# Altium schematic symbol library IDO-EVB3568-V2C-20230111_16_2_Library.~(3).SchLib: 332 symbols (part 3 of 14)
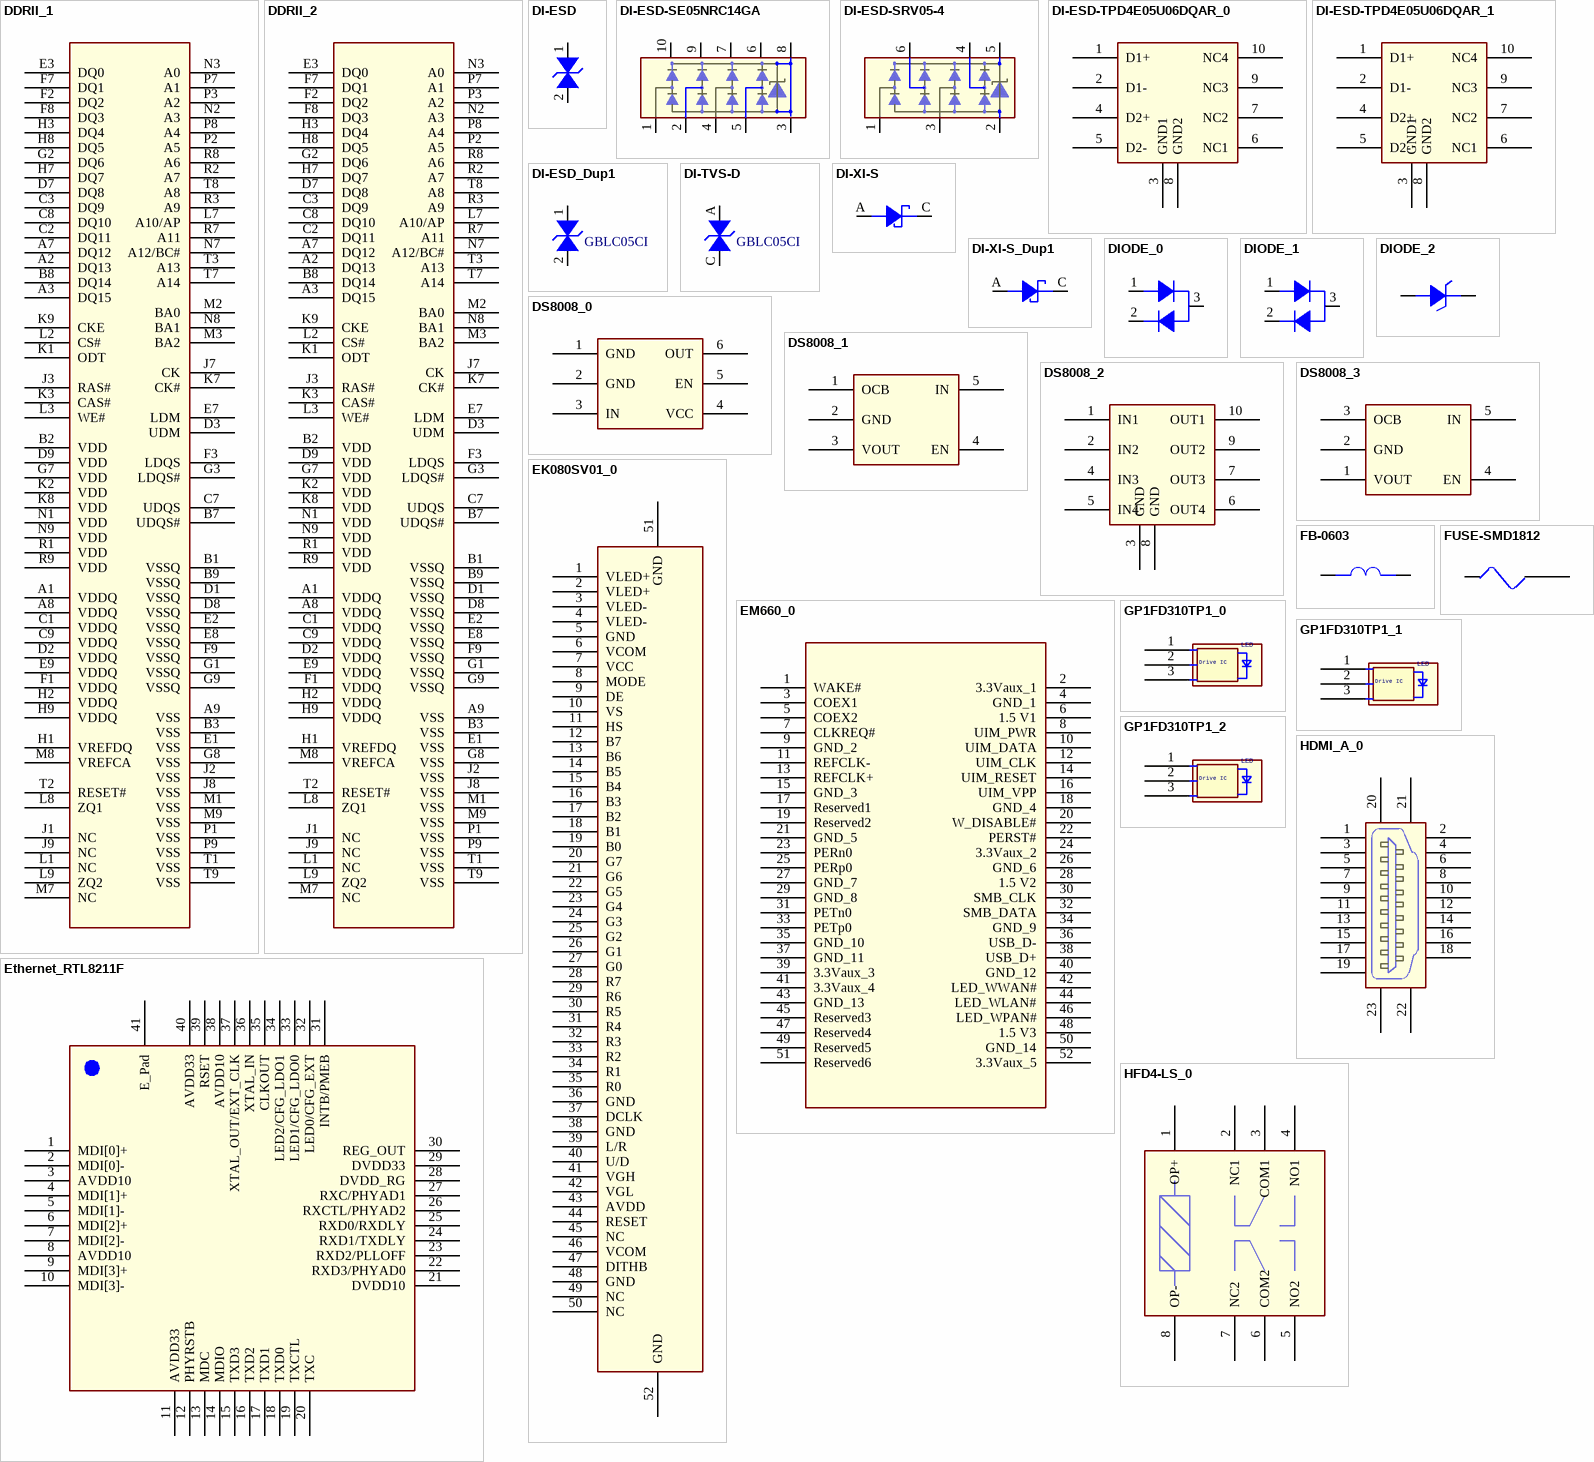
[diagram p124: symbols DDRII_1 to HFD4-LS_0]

## DIODE_1
designator D?
Altium-Right: 30; Altium-Bottom: 40
pins: 1 ANODE, 2 CATHODE, 3 COMMON

## DIODE_2
designator D?
Altium-Right: 30; Altium-Bottom: 20
pins: 1 A, 2 K

## DS8008_0
designator U?
Altium-Right: 70; Altium-Bottom: 60
pins: 1 GND, 2 GND, 3 IN, 4 VCC, 5 EN, 6 OUT

## DS8008_1
designator U?
Altium-Right: 70; Altium-Bottom: 60
pins: 1 OCB, 2 GND, 3 VOUT, 4 EN, 5 IN

## DS8008_2
designator U?
Altium-Right: 70; Altium-Bottom: 80
pins: 1 IN1, 2 IN2, 3 GND (power), 4 IN3, 5 IN4, 6 OUT4, 7 OUT3, 8 GND, 9 OUT2, 10 OUT1

## DS8008_3
designator U?
Altium-Right: 70; Altium-Bottom: 60
pins: 1 VOUT, 2 GND, 3 OCB, 4 EN, 5 IN

## EK080SV01_0
designator J?
Altium-Right: 70; Altium-Bottom: 550
pins: 1 VLED+, 2 VLED+, 3 VLED-, 4 VLED-, 5 GND, 6 VCOM, 7 VCC, 8 MODE, 9 DE, 10 VS, 11 HS, 12 B7, 13 B6, 14 B5, 15 B4, 16 B3, 17 B2, 18 B1, 19 B0, 20 G7, 21 G6, 22 G5, 23 G4, 24 G3, 25 G2, 26 G1, 27 G0, 28 R7, 29 R6, 30 R5, 31 R4, 32 R3, 33 R2, 34 R1, 35 R0, 36 GND, 37 DCLK, 38 GND, 39 L/R, 40 U/D, 41 VGH, 42 VGL, 43 AVDD, 44 RESET, 45 NC, 46 VCOM, 47 DITHB, 48 GND, 49 NC, 50 NC, 51 GND, 52 GND

## EM660_0
designator U?
Altium-Right: 160; Altium-Bottom: 310
pins: 1 WAKE#, 2 3.3Vaux_1 (power), 3 COEX1, 4 GND_1 (power), 5 COEX2, 6 1.5 V1, 7 CLKREQ#, 8 UIM_PWR, 9 GND_2 (power), 10 UIM_DATA, 11 REFCLK-, 12 UIM_CLK, 13 REFCLK+, 14 UIM_RESET, 15 GND_3 (power), 16 UIM_VPP, 17 Reserved1, 18 GND_4 (power), 19 Reserved2, 20 W_DISABLE#, 21 GND_5 (power), 22 PERST#, 23 PERn0, 24 3.3Vaux_2 (power), 25 PERp0, 26 GND_6 (power), 27 GND_7 (power), 28 1.5 V2, 29 GND_8 (power), 30 SMB_CLK, 31 PETn0, 32 SMB_DATA, 33 PETp0, 34 GND_9 (power), 35 GND_10 (power), 36 USB_D-, 37 GND_11 (power), 38 USB_D+, 39 3.3Vaux_3 (power), 40 GND_12, 41 3.3Vaux_4 (power), 42 LED_WWAN#, 43 GND_13 (power), 44 LED_WLAN#, 45 Reserved3, 46 LED_WPAN#, 47 Reserved4, 48 1.5 V3, 49 Reserved5, 50 GND_14 (power), 51 Reserved6, 52 3.3Vaux_5 (power)

## Ethernet_RTL8211F
designator U?
Altium-Right: 230
footprint QFN40_5R00X5R00X0R80_T
pins: 1 MDI[0]+, 2 MDI[0]-, 3 AVDD10 (power), 4 MDI[1]+, 5 MDI[1]-, 6 MDI[2]+, 7 MDI[2]-, 8 AVDD10 (power), 9 MDI[3]+, 10 MDI[3]-, 11 AVDD33 (power), 12 PHYRSTB, 13 MDC, 14 MDIO, 15 TXD3, 16 TXD2, 17 TXD1, 18 TXD0, 19 TXCTL, 20 TXC, 21 DVDD10 (power), 22 RXD3/PHYAD0, 23 RXD2/PLLOFF, 24 RXD1/TXDLY, 25 RXD0/RXDLY, 26 RXCTL/PHYAD2, 27 RXC/PHYAD1, 28 DVDD_RG, 29 DVDD33 (power), 30 REG_OUT, 31 INTB/PMEB, 32 LED0/CFG_EXT, 33 LED1/CFG_LDO0, 34 LED2/CFG_LDO1, 35 CLKOUT, 36 XTAL_IN, 37 XTAL_OUT/EXT_CLK, 38 AVDD10 (power), 39 RSET, 40 AVDD33 (power), 41 E_Pad

## FB-0603
designator FB?
SMD Multilayer Ferrite Chip Bead,3A,30Ohm,0.03R; Part Number: EL4.300Y060300A; Manufacture P/N: PZ1608D300-3R0TF; Manufacture2 P/N: PBY160808T-400Y-N; Manufacturer: SUNLORD; PN Type: SMD FERRITE BEAD; Altium-Right: 40; Altium-Bottom: 20
pins: 1, 2

## FUSE-SMD1812
designator F?
Altium-Right: 30; Altium-Bottom: 20
pins: 1, 2

## GP1FD310TP1_0
designator U?
Altium-Right: 50; Altium-Bottom: 40
pins: 1 GND, 2 Vcc, 3 VIN

## GP1FD310TP1_1
designator U?
Altium-Right: 50; Altium-Bottom: 40
pins: 1 GND, 2 Vcc, 3 VIN

## GP1FD310TP1_2
designator U?
Altium-Right: 50; Altium-Bottom: 40
pins: 1 GND, 2 Vcc, 3 VIN

## HDMI_A_0
designator J?
Altium-Right: 40; Altium-Bottom: 110
pins: 1 $PIN0, 2, 3, 4, 5, 6, 7, 8, 9, 10, 11, 12, 13, 14, 15, 16, 17, 18, 19, 20, 21, 22, 23

## HFD4-LS_0
designator M?
Altium-Right: 120; Altium-Bottom: 110
pins: 1 OP+, 2 NC1, 3 COM1, 4 NO1, 5 NO2, 6 COM2, 7 NC2, 8 OP-

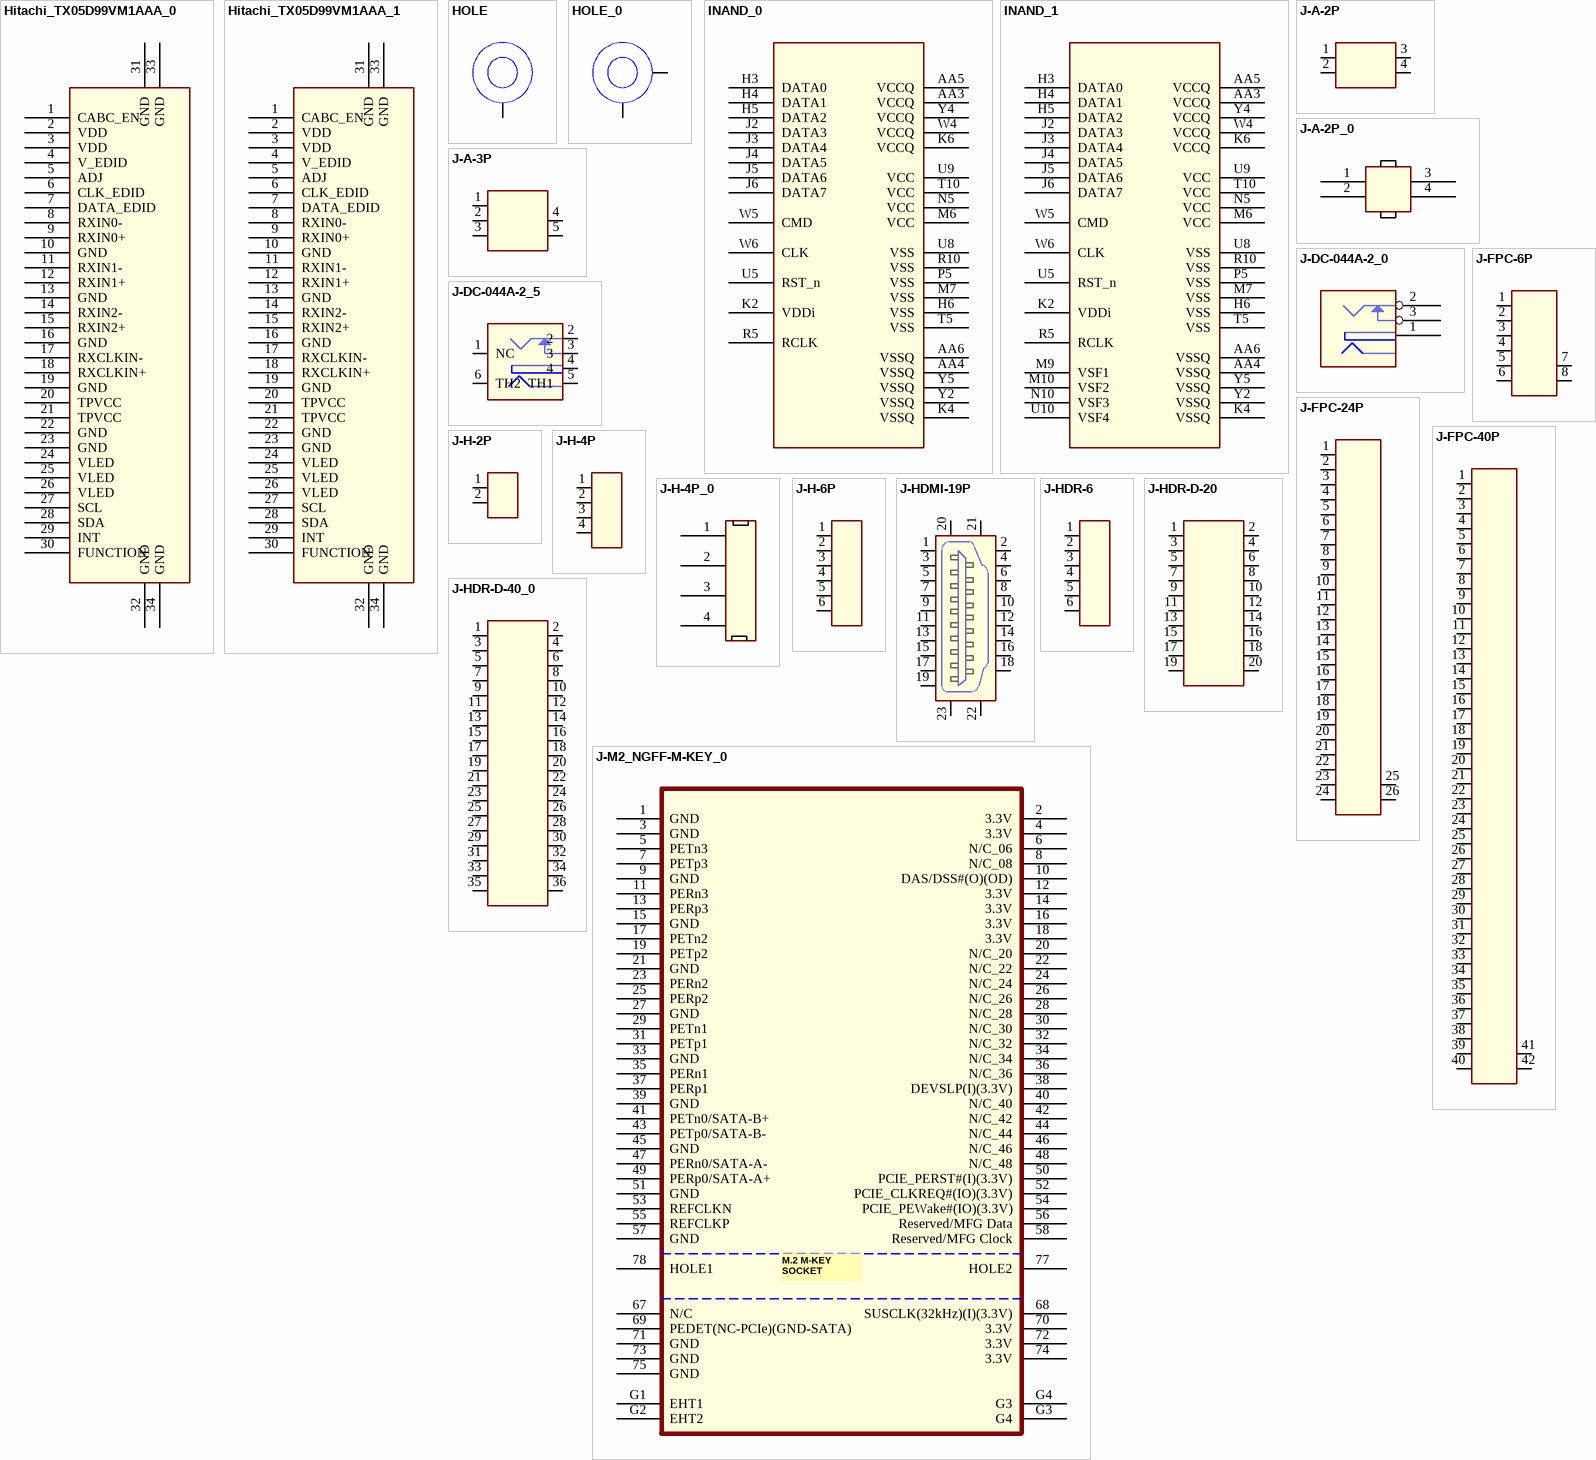
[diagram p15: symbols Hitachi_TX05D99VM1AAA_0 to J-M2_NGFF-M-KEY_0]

## Hitachi_TX05D99VM1AAA_0
designator CON?
Altium-Right: 80; Altium-Bottom: 330
pins: 1 CABC_EN, 2 VDD, 3 VDD, 4 V_EDID, 5 ADJ, 6 CLK_EDID, 7 DATA_EDID, 8 RXIN0-, 9 RXIN0+, 10 GND, 11 RXIN1-, 12 RXIN1+, 13 GND, 14 RXIN2-, 15 RXIN2+, 16 GND, 17 RXCLKIN-, 18 RXCLKIN+, 19 GND, 20 TPVCC, 21 TPVCC, 22 GND, 23 GND, 24 VLED, 25 VLED, 26 VLED, 27 SCL, 28 SDA, 29 INT, 30 FUNCTION, 31 GND, 32 GND, 33 GND, 34 GND

## Hitachi_TX05D99VM1AAA_1
designator CON?
Altium-Right: 80; Altium-Bottom: 330
pins: 1 CABC_EN, 2 VDD, 3 VDD, 4 V_EDID, 5 ADJ, 6 CLK_EDID, 7 DATA_EDID, 8 RXIN0-, 9 RXIN0+, 10 GND, 11 RXIN1-, 12 RXIN1+, 13 GND, 14 RXIN2-, 15 RXIN2+, 16 GND, 17 RXCLKIN-, 18 RXCLKIN+, 19 GND, 20 TPVCC, 21 TPVCC, 22 GND, 23 GND, 24 VLED, 25 VLED, 26 VLED, 27 SCL, 28 SDA, 29 INT, 30 FUNCTION, 31 GND, 32 GND, 33 GND, 34 GND

## HOLE
designator H?  (value not drawn)
Altium-Right: 40
pins: 1

## HOLE_0
designator H?  (value not drawn)
Altium-Right: 40
pins: 1, 2

## INAND_0
designator U?
Altium-Right: 100; Altium-Bottom: 270
footprint INANA-BGA169
pins: AA3 VCCQ (power), AA4 VSSQ (power), AA5 VCCQ (power), AA6 VSSQ (power), H3 DATA0, H4 DATA1, H5 DATA2, H6 VSS (power), J2 DATA3, J3 DATA4, J4 DATA5, J5 DATA6, J6 DATA7, K2 VDDi, K4 VSSQ (power), K6 VCCQ (power), M6 VCC (power), M7 VSS (power), N5 VCC (power), P5 VSS (power), R5 RCLK, R10 VSS (power), T5 VSS (power), T10 VCC (power), U5 RST_n, U8 VSS (power), U9 VCC (power), W4 VCCQ (power), W5 CMD, W6 CLK, Y2 VSSQ (power), Y4 VCCQ (power), Y5 VSSQ (power)

## INAND_1
designator U?
Altium-Right: 100; Altium-Bottom: 270
footprint INANA-BGA169
pins: AA3 VCCQ (power), AA4 VSSQ (power), AA5 VCCQ (power), AA6 VSSQ (power), H3 DATA0, H4 DATA1, H5 DATA2, H6 VSS (power), J2 DATA3, J3 DATA4, J4 DATA5, J5 DATA6, J6 DATA7, K2 VDDi, K4 VSSQ (power), K6 VCCQ (power), M6 VCC (power), M7 VSS (power), M9 VSF1, M10 VSF2, N5 VCC (power), N10 VSF3, P5 VSS (power), R5 RCLK, R10 VSS (power), T5 VSS (power), T10 VCC (power), U5 RST_n, U8 VSS (power), U9 VCC (power), U10 VSF4, W4 VCCQ (power), W5 CMD, W6 CLK, Y2 VSSQ (power), Y4 VCCQ (power), Y5 VSSQ (power)

## J-A-2P
designator J?
Altium-Right: 40; Altium-Bottom: 30
pins: 1, 2, 3, 4

## J-A-2P_0
designator J?
Altium-Right: 30; Altium-Bottom: 50
pins: 1, 2, 3, 4

## J-A-3P
designator J?
Altium-Right: 40
pins: 1, 2, 3, 4, 5

## J-DC-044A-2_0
designator J?
Altium-Right: 50; Altium-Bottom: 51
pins: 1, 2, 3

## J-DC-044A-2_5
designator J?
Altium-Right: 50; Altium-Bottom: 51
pins: 1 NC, 2, 3, 4, 5 TH1, 6 TH2

## J-FPC-6P
designator J?
Altium-Right: 30; Altium-Bottom: 70
pins: 1, 2, 3, 4, 5, 6, 7, 8

## J-FPC-24P
designator J?
Altium-Right: 30; Altium-Bottom: 250
pins: 1, 2, 3, 4, 5, 6, 7, 8, 9, 10, 11, 12, 13, 14, 15, 16, 17, 18, 19, 20, 21, 22, 23, 24, 25, 26

## J-FPC-40P
designator J?
Altium-Right: 30; Altium-Bottom: 410
pins: 1, 2, 3, 4, 5, 6, 7, 8, 9, 10, 11, 12, 13, 14, 15, 16, 17, 18, 19, 20, 21, 22, 23, 24, 25, 26, 27, 28, 29, 30, 31, 32, 33, 34, 35, 36, 37, 38, 39, 40, 41, 42

## J-H-2P
designator J?
Altium-Right: 20; Altium-Bottom: 30
pins: 1, 2

## J-H-4P
designator J?
Altium-Right: 20; Altium-Bottom: 50
pins: 1, 2, 3, 4

## J-H-4P_0
designator J?
Altium-Right: 20; Altium-Bottom: 80
pins: 1, 2, 3, 4

## J-H-6P
designator J?
Altium-Right: 20; Altium-Bottom: 70
pins: 1, 2, 3, 4, 5, 6

## J-HDMI-19P
designator J?
Altium-Right: 40; Altium-Bottom: 110
pins: 1 $PIN0, 2, 3, 4, 5, 6, 7, 8, 9, 10, 11, 12, 13, 14, 15, 16, 17, 18, 19, 20, 21, 22, 23

## J-HDR-6
designator J?
Altium-Right: 20; Altium-Bottom: 70
pins: 1, 2, 3, 4, 5, 6

## J-HDR-D-20
designator J?
Altium-Right: 40; Altium-Bottom: 110
pins: 1, 2, 3, 4, 5, 6, 7, 8, 9, 10, 11, 12, 13, 14, 15, 16, 17, 18, 19, 20

## J-HDR-D-40_0
designator J?
Altium-Right: 40; Altium-Bottom: 190
pins: 1, 2, 3, 4, 5, 6, 7, 8, 9, 10, 11, 12, 13, 14, 15, 16, 17, 18, 19, 20, 21, 22, 23, 24, 25, 26, 27, 28, 29, 30, 31, 32, 33, 34, 35, 36

## J-M2_NGFF-M-KEY_0
designator J?
Altium-Right: 240; Altium-Bottom: 430
pins: 1 GND (power), 2 3.3V (power), 3 GND (power), 4 3.3V (power), 5 PETn3, 6 N/C_06, 7 PETp3, 8 N/C_08, 9 GND (power), 10 DAS/DSS#(O)(OD), 11 PERn3, 12 3.3V (power), 13 PERp3, 14 3.3V (power), 15 GND (power), 16 3.3V (power), 17 PETn2, 18 3.3V (power), 19 PETp2, 20 N/C_20, 21 GND (power), 22 N/C_22, 23 PERn2, 24 N/C_24, 25 PERp2, 26 N/C_26, 27 GND (power), 28 N/C_28, 29 PETn1, 30 N/C_30, 31 PETp1, 32 N/C_32, 33 GND (power), 34 N/C_34, 35 PERn1, 36 N/C_36, 37 PERp1, 38 DEVSLP(I)(3.3V), 39 GND (power), 40 N/C_40, 41 PETn0/SATA-B+, 42 N/C_42, 43 PETp0/SATA-B-, 44 N/C_44, 45 GND (power), 46 N/C_46, 47 PERn0/SATA-A-, 48 N/C_48, 49 PERp0/SATA-A+, 50 PCIE_PERST#(I)(3.3V), 51 GND (power), 52 PCIE_CLKREQ#(IO)(3.3V), 53 REFCLKN, 54 PCIE_PEWake#(IO)(3.3V), 55 REFCLKP, 56 Reserved/MFG Data, 57 GND (power), 58 Reserved/MFG Clock, 67 N/C, 68 SUSCLK(32kHz)(I)(3.3V), 69 PEDET(NC-PCIe)(GND-SATA), 70 3.3V (power), 71 GND (power), 72 3.3V (power), 73 GND (power), 74 3.3V (power), 75 GND (power), 77 HOLE2 (power), 78 HOLE1 (power), G1 EHT1, G2 EHT2, G3 G4, G4 G3

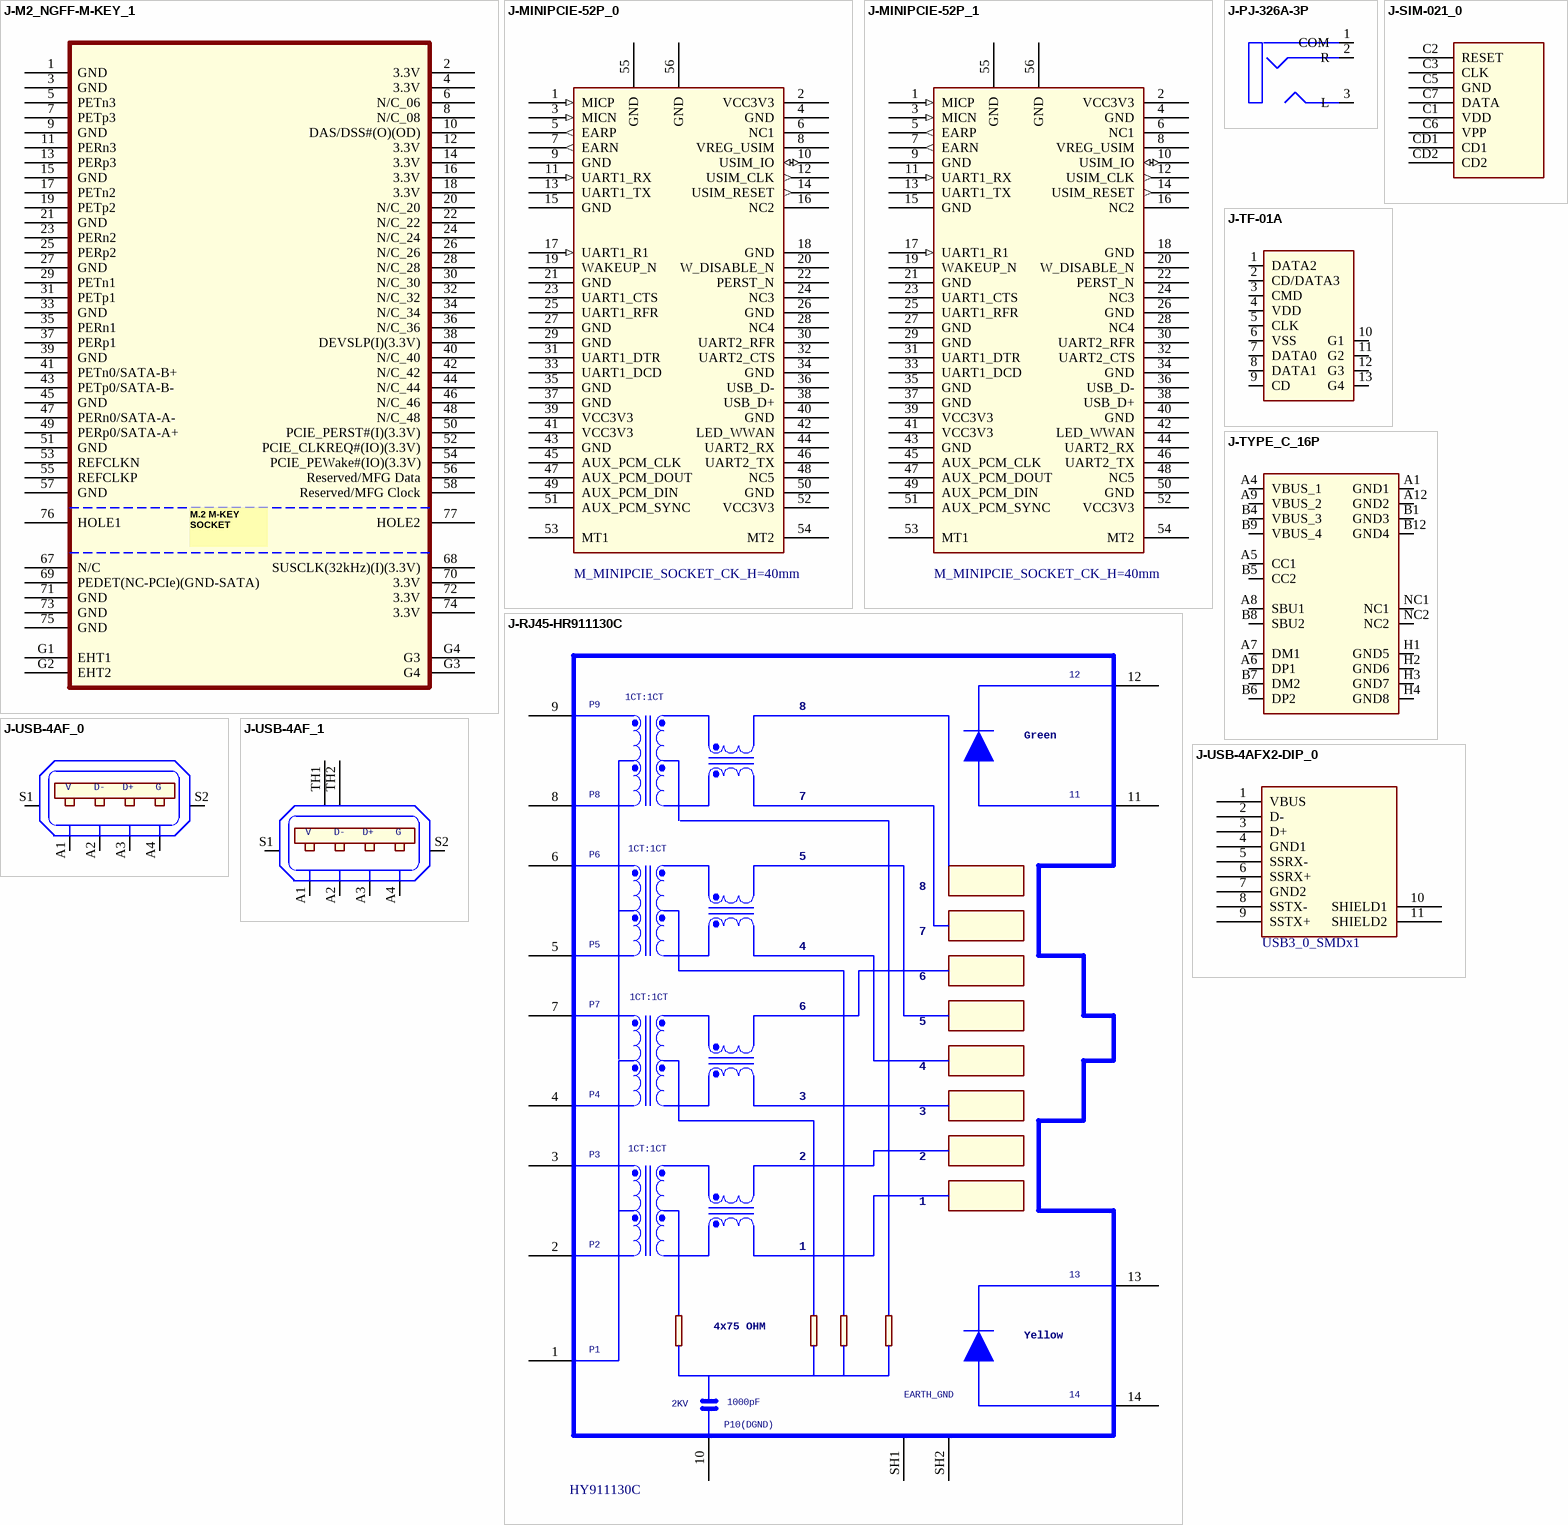
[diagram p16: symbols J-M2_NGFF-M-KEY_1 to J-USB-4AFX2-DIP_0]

## J-M2_NGFF-M-KEY_1
designator J?
Altium-Right: 240; Altium-Bottom: 430
pins: 1 GND (power), 2 3.3V (power), 3 GND (power), 4 3.3V (power), 5 PETn3, 6 N/C_06, 7 PETp3, 8 N/C_08, 9 GND (power), 10 DAS/DSS#(O)(OD), 11 PERn3, 12 3.3V (power), 13 PERp3, 14 3.3V (power), 15 GND (power), 16 3.3V (power), 17 PETn2, 18 3.3V (power), 19 PETp2, 20 N/C_20, 21 GND (power), 22 N/C_22, 23 PERn2, 24 N/C_24, 25 PERp2, 26 N/C_26, 27 GND (power), 28 N/C_28, 29 PETn1, 30 N/C_30, 31 PETp1, 32 N/C_32, 33 GND (power), 34 N/C_34, 35 PERn1, 36 N/C_36, 37 PERp1, 38 DEVSLP(I)(3.3V), 39 GND (power), 40 N/C_40, 41 PETn0/SATA-B+, 42 N/C_42, 43 PETp0/SATA-B-, 44 N/C_44, 45 GND (power), 46 N/C_46, 47 PERn0/SATA-A-, 48 N/C_48, 49 PERp0/SATA-A+, 50 PCIE_PERST#(I)(3.3V), 51 GND (power), 52 PCIE_CLKREQ#(IO)(3.3V), 53 REFCLKN, 54 PCIE_PEWake#(IO)(3.3V), 55 REFCLKP, 56 Reserved/MFG Data, 57 GND (power), 58 Reserved/MFG Clock, 67 N/C, 68 SUSCLK(32kHz)(I)(3.3V), 69 PEDET(NC-PCIe)(GND-SATA), 70 3.3V (power), 71 GND (power), 72 3.3V (power), 73 GND (power), 74 3.3V (power), 75 GND (power), 76 HOLE1 (power), 77 HOLE2 (power), G1 EHT1, G2 EHT2, G3 G4, G4 G3

## J-MINIPCIE-52P_0
designator MINI-PCIE?, comment M_MINIPCIE_SOCKET_CK_H=40mm
CLASS: IO; Altium-Right: 140; Altium-Bottom: 310
pins: 1 MICP (in), 2 VCC3V3 (power), 3 MICN (in), 4 GND (power), 5 EARP (out), 6 NC1, 7 EARN (out), 8 VREG_USIM (power), 9 GND (power), 10 USIM_IO (io), 11 UART1_RX (in), 12 USIM_CLK (out), 13 UART1_TX, 14 USIM_RESET (out), 15 GND (power), 16 NC2, 17 UART1_R1 (in), 18 GND (power), 19 WAKEUP_N, 20 W_DISABLE_N, 21 GND (power), 22 PERST_N, 23 UART1_CTS, 24 NC3, 25 UART1_RFR, 26 GND (power), 27 GND (power), 28 NC4, 29 GND (power), 30 UART2_RFR, 31 UART1_DTR, 32 UART2_CTS, 33 UART1_DCD, 34 GND (power), 35 GND (power), 36 USB_D-, 37 GND (power), 38 USB_D+, 39 VCC3V3 (power), 40 GND (power), 41 VCC3V3 (power), 42 LED_WWAN, 43 GND (power), 44 UART2_RX, 45 AUX_PCM_CLK, 46 UART2_TX, 47 AUX_PCM_DOUT, 48 NC5, 49 AUX_PCM_DIN, 50 GND (power), 51 AUX_PCM_SYNC, 52 VCC3V3 (power), 53 MT1, 54 MT2, 55 GND, 56 GND

## J-MINIPCIE-52P_1
designator MINI-PCIE?, comment M_MINIPCIE_SOCKET_CK_H=40mm
CLASS: IO; Altium-Right: 140; Altium-Bottom: 310
pins: 1 MICP (in), 2 VCC3V3 (power), 3 MICN (in), 4 GND (power), 5 EARP (out), 6 NC1, 7 EARN (out), 8 VREG_USIM (power), 9 GND (power), 10 USIM_IO (io), 11 UART1_RX (in), 12 USIM_CLK (out), 13 UART1_TX, 14 USIM_RESET (out), 15 GND (power), 16 NC2, 17 UART1_R1 (in), 18 GND (power), 19 WAKEUP_N, 20 W_DISABLE_N, 21 GND (power), 22 PERST_N, 23 UART1_CTS, 24 NC3, 25 UART1_RFR, 26 GND (power), 27 GND (power), 28 NC4, 29 GND (power), 30 UART2_RFR, 31 UART1_DTR, 32 UART2_CTS, 33 UART1_DCD, 34 GND (power), 35 GND (power), 36 USB_D-, 37 GND (power), 38 USB_D+, 39 VCC3V3 (power), 40 GND (power), 41 VCC3V3 (power), 42 LED_WWAN, 43 GND (power), 44 UART2_RX, 45 AUX_PCM_CLK, 46 UART2_TX, 47 AUX_PCM_DOUT, 48 NC5, 49 AUX_PCM_DIN, 50 GND (power), 51 AUX_PCM_SYNC, 52 VCC3V3 (power), 53 MT1, 54 MT2, 55 GND (power), 56 GND (power)

## J-PJ-326A-3P
designator AU?
P/N: 182K00300S; Altium-Right: 60
pins: 1 COM, 2 R, 3 L

## J-RJ45-HR911130C
designator RJ45?, comment HY911130C
Altium-Right: 360; Altium-Bottom: 520
pins: 1 CT1/2/3/4, 2 MDI_0+, 3 MDI_0-, 4 MDI_1+, 5 MDI_2+, 6 MDI_2-, 7 MDI_1-, 8 MDI_3+, 9 MDI_3-, 10 GND, 11 G_LED+, 12 G_LED-, 13 Y_LED-, 14 Y_LED+, SH1, SH2

## J-SIM-021_0
designator J?
Altium-Right: 60; Altium-Bottom: 90
pins: C1 VDD, C2 RESET, C3 CLK, C5 GND, C6 VPP, C7 DATA, CD1, CD2

## J-TF-01A
designator J?
Altium-Right: 60; Altium-Bottom: 100
pins: 1 DATA2, 2 CD/DATA3, 3 CMD, 4 VDD, 5 CLK, 6 VSS, 7 DATA0, 8 DATA1, 9 CD, 10 G1, 11 G2, 12 G3, 13 G4

## J-TYPE_C_16P
designator J?
Altium-Right: 90; Altium-Bottom: 160
pins: A1 GND1, A4 VBUS_1, A5 CC1, A6 DP1, A7 DM1, A8 SBU1, A9 VBUS_2, A12 GND2, B1 GND3, B4 VBUS_3, B5 CC2, B6 DP2, B7 DM2, B8 SBU2, B9 VBUS_4, B12 GND4, H1 GND5, H2 GND6, H3 GND7, H4 GND8, NC1, NC2

## J-USB-4AF_0
designator J?
CLASS: IO; Altium-Right: 100; Altium-Bottom: 50
footprint USB_A_SMT
pins: A1 VCC, A2 DATA+, A3 DATA-, A4 GND, S1 SGND1, S2 SGND2

## J-USB-4AF_1
designator J?
CLASS: IO; Altium-Right: 100; Altium-Bottom: 50
footprint USB_A_SMT
pins: A1 VCC, A2 DATA+, A3 DATA-, A4 GND, S1 SGND1, S2 SGND2, TH1 SGND3, TH2 SGND4

## J-USB-4AFX2-DIP_0
designator USB?, comment USB3_0_SMDx1
USB,TYPE-A,2PORT,R/A,W/SHIELD; VSTNO: H00025; Altium-Right: 90; Altium-Bottom: 100
pins: 1 VBUS, 2 D-, 3 D+, 4 GND1, 5 SSRX-, 6 SSRX+, 7 GND2, 8 SSTX-, 9 SSTX+, 10 SHIELD1, 11 SHIELD2

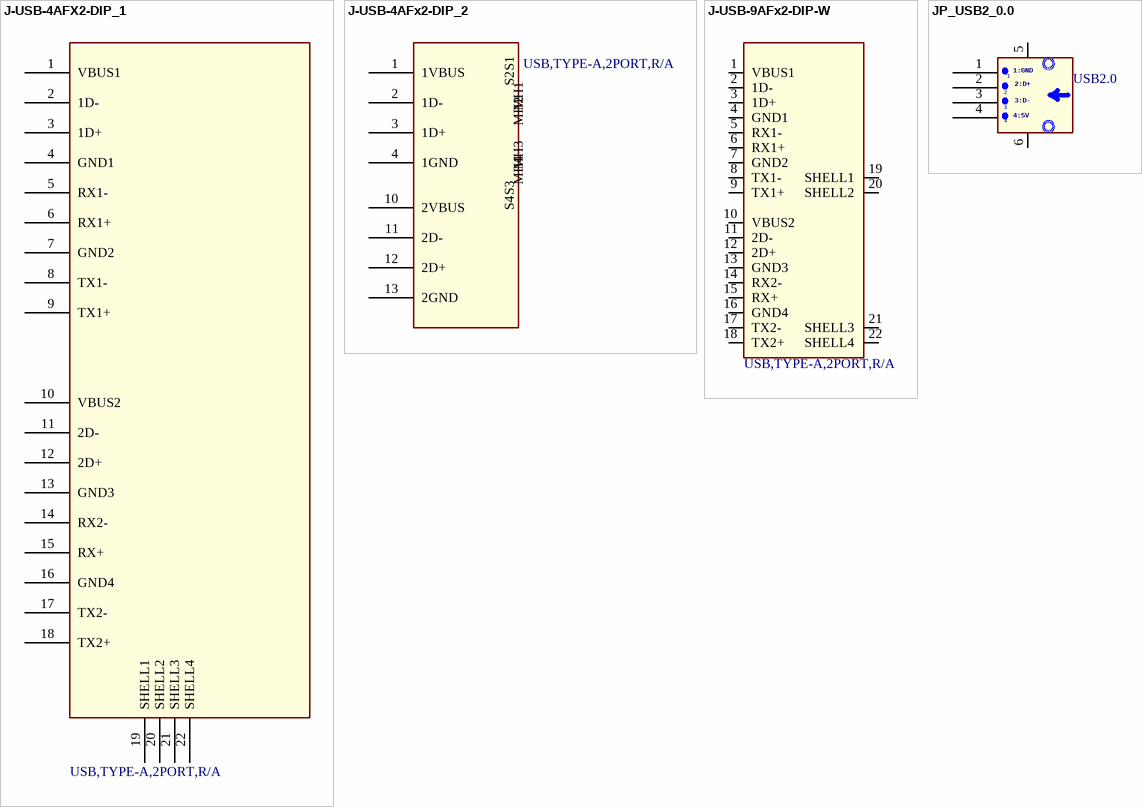
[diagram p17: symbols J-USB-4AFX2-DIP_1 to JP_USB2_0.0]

## J-USB-4AFX2-DIP_1
designator USB?, comment USB,TYPE-A,2PORT,R/A
USB,TYPE-A,2PORT,R/A,W/SHIELD; VSTNO: H00025; Altium-Right: 160; Altium-Bottom: 450
pins: 1 VBUS1, 2 1D-, 3 1D+, 4 GND1, 5 RX1-, 6 RX1+, 7 GND2, 8 TX1-, 9 TX1+, 10 VBUS2, 11 2D-, 12 2D+, 13 GND3, 14 RX2-, 15 RX+, 16 GND4, 17 TX2-, 18 TX2+, 19 SHELL1, 20 SHELL2, 21 SHELL3, 22 SHELL4

## J-USB-4AFx2-DIP_2
designator USB?, comment USB,TYPE-A,2PORT,R/A
USB,TYPE-A,2PORT,R/A,W/SHIELD; VSTNO: H00025; Altium-Right: 70; Altium-Bottom: 190
pins: 1 1VBUS, 2 1D-, 3 1D+, 4 1GND, 10 2VBUS, 11 2D-, 12 2D+, 13 2GND, S1 MH1, S2 MH2, S3 MH3, S4 MH4

## J-USB-9AFx2-DIP-W
designator J?, comment USB,TYPE-A,2PORT,R/A
USB,TYPE-A,2PORT,R/A,W/SHIELD; VSTNO: H00025; Altium-Right: 80; Altium-Bottom: 210
pins: 1 VBUS1, 2 1D-, 3 1D+, 4 GND1, 5 RX1-, 6 RX1+, 7 GND2, 8 TX1-, 9 TX1+, 10 VBUS2, 11 2D-, 12 2D+, 13 GND3, 14 RX2-, 15 RX+, 16 GND4, 17 TX2-, 18 TX2+, 19 SHELL1, 20 SHELL2, 21 SHELL3, 22 SHELL4

## JP_USB2_0.0
designator USB?, comment USB2.0
PCB Footprint: USB20; Altium-Right: 50
footprint USB20
pins: 1, 2, 3, 4, 5, 6

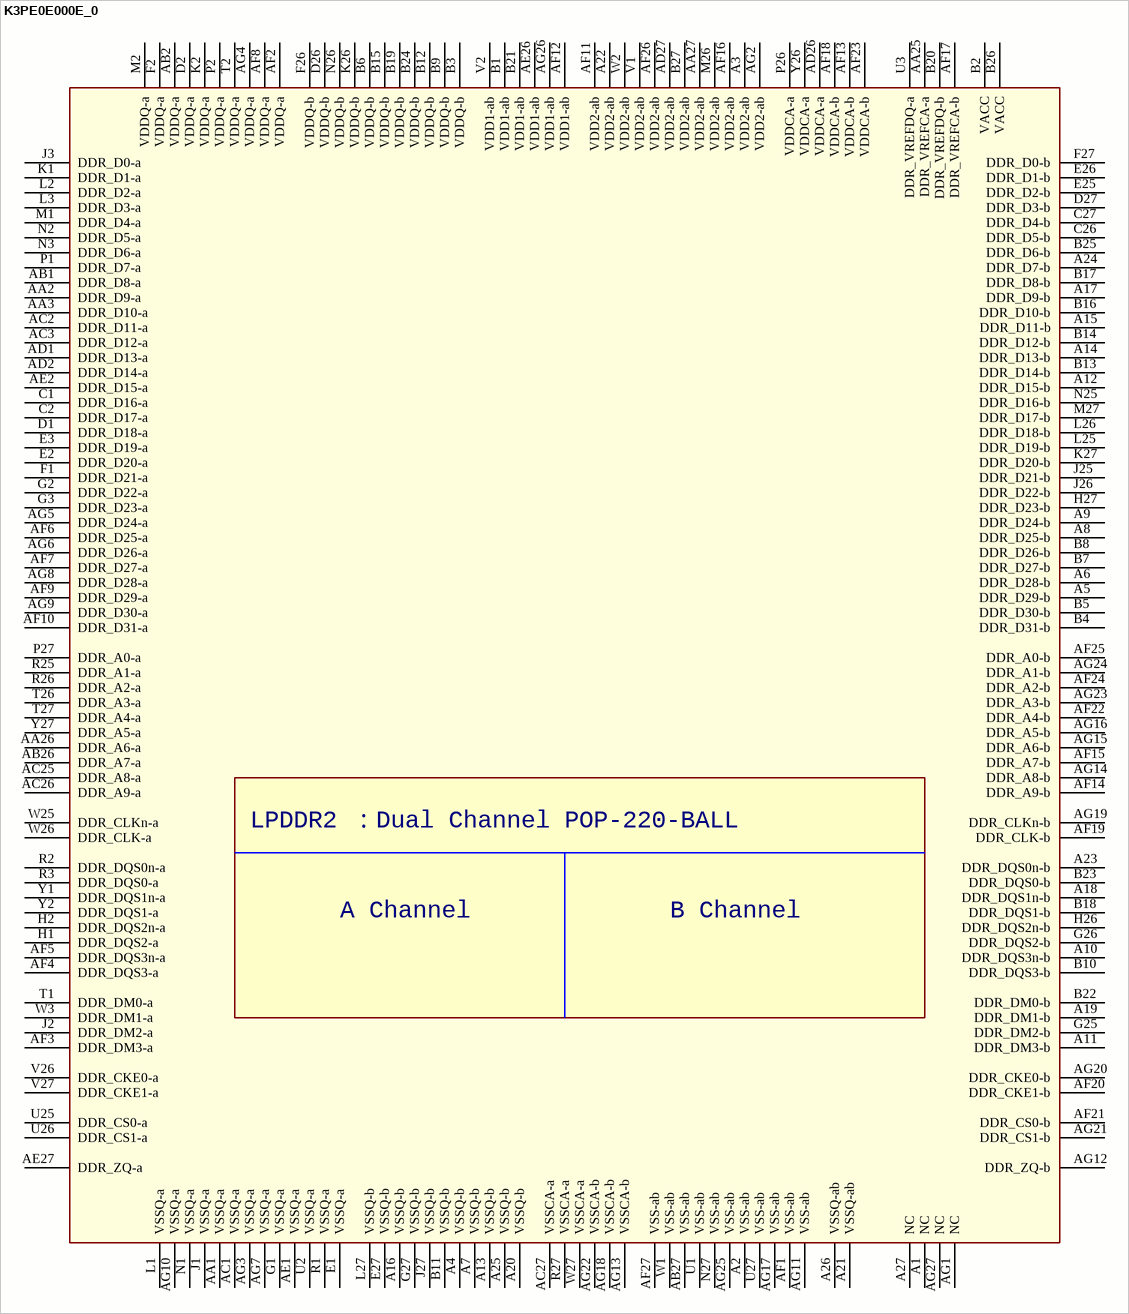
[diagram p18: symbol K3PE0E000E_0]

## K3PE0E000E_0
designator U?
Altium-Right: 660; Altium-Bottom: 770
footprint FBGA220-14X14
pins: A1 NC, A2 VSS-ab, A3 VDD2-ab, A4 VSSQ-b, A5 DDR_D29-b, A6 DDR_D28-b, A7 VSSQ-b, A8 DDR_D25-b, A9 DDR_D24-b, A10 DDR_DQS3n-b, A11 DDR_DM3-b, A12 DDR_D15-b, A13 VSSQ-b, A14 DDR_D13-b, A15 DDR_D11-b, A16 VSSQ-b, A17 DDR_D9-b, A18 DDR_DQS1n-b, A19 DDR_DM1-b, A20 VSSQ-b, A21 VSSQ-ab, A22 VDD2-ab, A23 DDR_DQS0n-b, A24 DDR_D7-b, A25 VSSQ-b, A26 VSSQ-ab, A27 NC, AA1 VSSQ-a, AA2 DDR_D9-a, AA3 DDR_D10-a, AA25 DDR_VREFCA-a, AA26 DDR_A6-a, AA27 VDD2-ab, AB1 DDR_D8-a, AB2 VDDQ-a, AB26 DDR_A7-a, AB27 VSS-ab, AC1 VSSQ-a, AC2 DDR_D11-a, AC3 DDR_D12-a, AC25 DDR_A8-a, AC26 DDR_A9-a, AC27 VSSCA-a, AD1 DDR_D13-a, AD2 DDR_D14-a, AD26 VDDCA-a, AD27 VDD2-ab, AE1 VSSQ-a, AE2 DDR_D15-a, AE26 VDD1-ab, AE27 DDR_ZQ-a, AF1 VSS-ab, AF2 VDDQ-a, AF3 DDR_DM3-a, AF4 DDR_DQS3-a, AF5 DDR_DQS3n-a, AF6 DDR_D25-a, AF7 DDR_D27-a, AF8 VDDQ-a, AF9 DDR_D29-a, AF10 DDR_D31-a, AF11 VDD2-ab, AF12 VDD1-ab, AF13 VDDCA-b, AF14 DDR_A9-b, AF15 DDR_A7-b, AF16 VDD2-ab, AF17 DDR_VREFCA-b, AF18 VDDCA-b, AF19 DDR_CLK-b, AF20 DDR_CKE1-b, AF21 DDR_CS0-b, AF22 DDR_A4-b, AF23 VDDCA-b, AF24 DDR_A2-b, AF25 DDR_A0-b, AF26 VDD2-ab, AF27 VSS-ab, AG1 NC, AG2 VDD2-ab, AG3 VSSQ-a, AG4 VDDQ-a, AG5 DDR_D24-a, AG6 DDR_D26-a, AG7 VSSQ-a, AG8 DDR_D28-a, AG9 DDR_D30-a, AG10 VSSQ-a, AG11 VSS-ab, AG12 DDR_ZQ-b, AG13 VSSCA-b, AG14 DDR_A8-b, AG15 DDR_A6-b, AG16 DDR_A5-b, AG17 VSS-ab, AG18 VSSCA-b, AG19 DDR_CLKn-b, AG20 DDR_CKE0-b, AG21 DDR_CS1-b, AG22 VSSCA-b, AG23 DDR_A3-b, AG24 DDR_A1-b, AG25 VSS-ab, AG26 VDD1-ab, AG27 NC, B1 VDD1-ab, B2 VACC, B3 VDDQ-b, B4 DDR_D31-b, B5 DDR_D30-b, B6 VDDQ-b, B7 DDR_D27-b, B8 DDR_D26-b, B9 VDDQ-b, B10 DDR_DQS3-b, B11 VSSQ-b, B12 VDDQ-b, B13 DDR_D14-b, B14 DDR_D12-b, B15 VDDQ-b, B16 DDR_D10-b, B17 DDR_D8-b, B18 DDR_DQS1-b, B19 VDDQ-b, B20 DDR_VREFDQ-b, B21 VDD1-ab, B22 DDR_DM0-b, B23 DDR_DQS0-b, B24 VDDQ-b, B25 DDR_D6-b, B26 VACC, B27 VDD2-ab, C1 DDR_D16-a, C2 DDR_D17-a, C26 DDR_D5-b, C27 DDR_D4-b, D1 DDR_D18-a, D2 VDDQ-a, D26 VDDQ-b, D27 DDR_D3-b, E1 VSSQ-a, E2 DDR_D20-a, E3 DDR_D19-a, E25 DDR_D2-b, E26 DDR_D1-b, E27 VSSQ-b, F1 DDR_D21-a, F2 VDDQ-a, F26 VDDQ-b, F27 DDR_D0-b, G1 VSSQ-a, G2 DDR_D22-a, G3 DDR_D23-a, G25 DDR_DM2-b, G26 DDR_DQS2-b, G27 VSSQ-b, H1 DDR_DQS2-a, H2 DDR_DQS2n-a, H26 DDR_DQS2n-b, H27 DDR_D23-b, J1 VSSQ-a, J2 DDR_DM2-a, J3 DDR_D0-a, J25 DDR_D21-b, J26 DDR_D22-b, J27 VSSQ-b, K1 DDR_D1-a, K2 VDDQ-a, K26 VDDQ-b, K27 DDR_D20-b, L1 VSSQ-a, L2 DDR_D2-a, L3 DDR_D3-a, L25 DDR_D19-b, L26 DDR_D18-b, L27 VSSQ-b, M1 DDR_D4-a, M2 VDDQ-a, M26 VDD2-ab, M27 DDR_D17-b, N1 VSSQ-a, N2 DDR_D5-a, N3 DDR_D6-a, N25 DDR_D16-b, N26 VDDQ-b, N27 VSS-ab, P1 DDR_D7-a, P2 VDDQ-a, P26 VDDCA-a, P27 DDR_A0-a, R1 VSSQ-a, R2 DDR_DQS0n-a, R3 DDR_DQS0-a, R25 DDR_A1-a, R26 DDR_A2-a, R27 VSSCA-a, T1 DDR_DM0-a, T2 VDDQ-a, T26 DDR_A3-a, T27 DDR_A4-a, U1 VSS-ab, U2 VSSQ-a, U3 DDR_VREFDQ-a, U25 DDR_CS0-a, U26 DDR_CS1-a, U27 VSS-ab, V1 VDD2-ab, V2 VDD1-ab, V26 DDR_CKE0-a, V27 DDR_CKE1-a, W1 VSS-ab, W2 VDD2-ab, W3 DDR_DM1-a, W25 DDR_CLKn-a, W26 DDR_CLK-a, W27 VSSCA-a, Y1 DDR_DQS1n-a, Y2 DDR_DQS1-a, Y26 VDDCA-a, Y27 DDR_A5-a

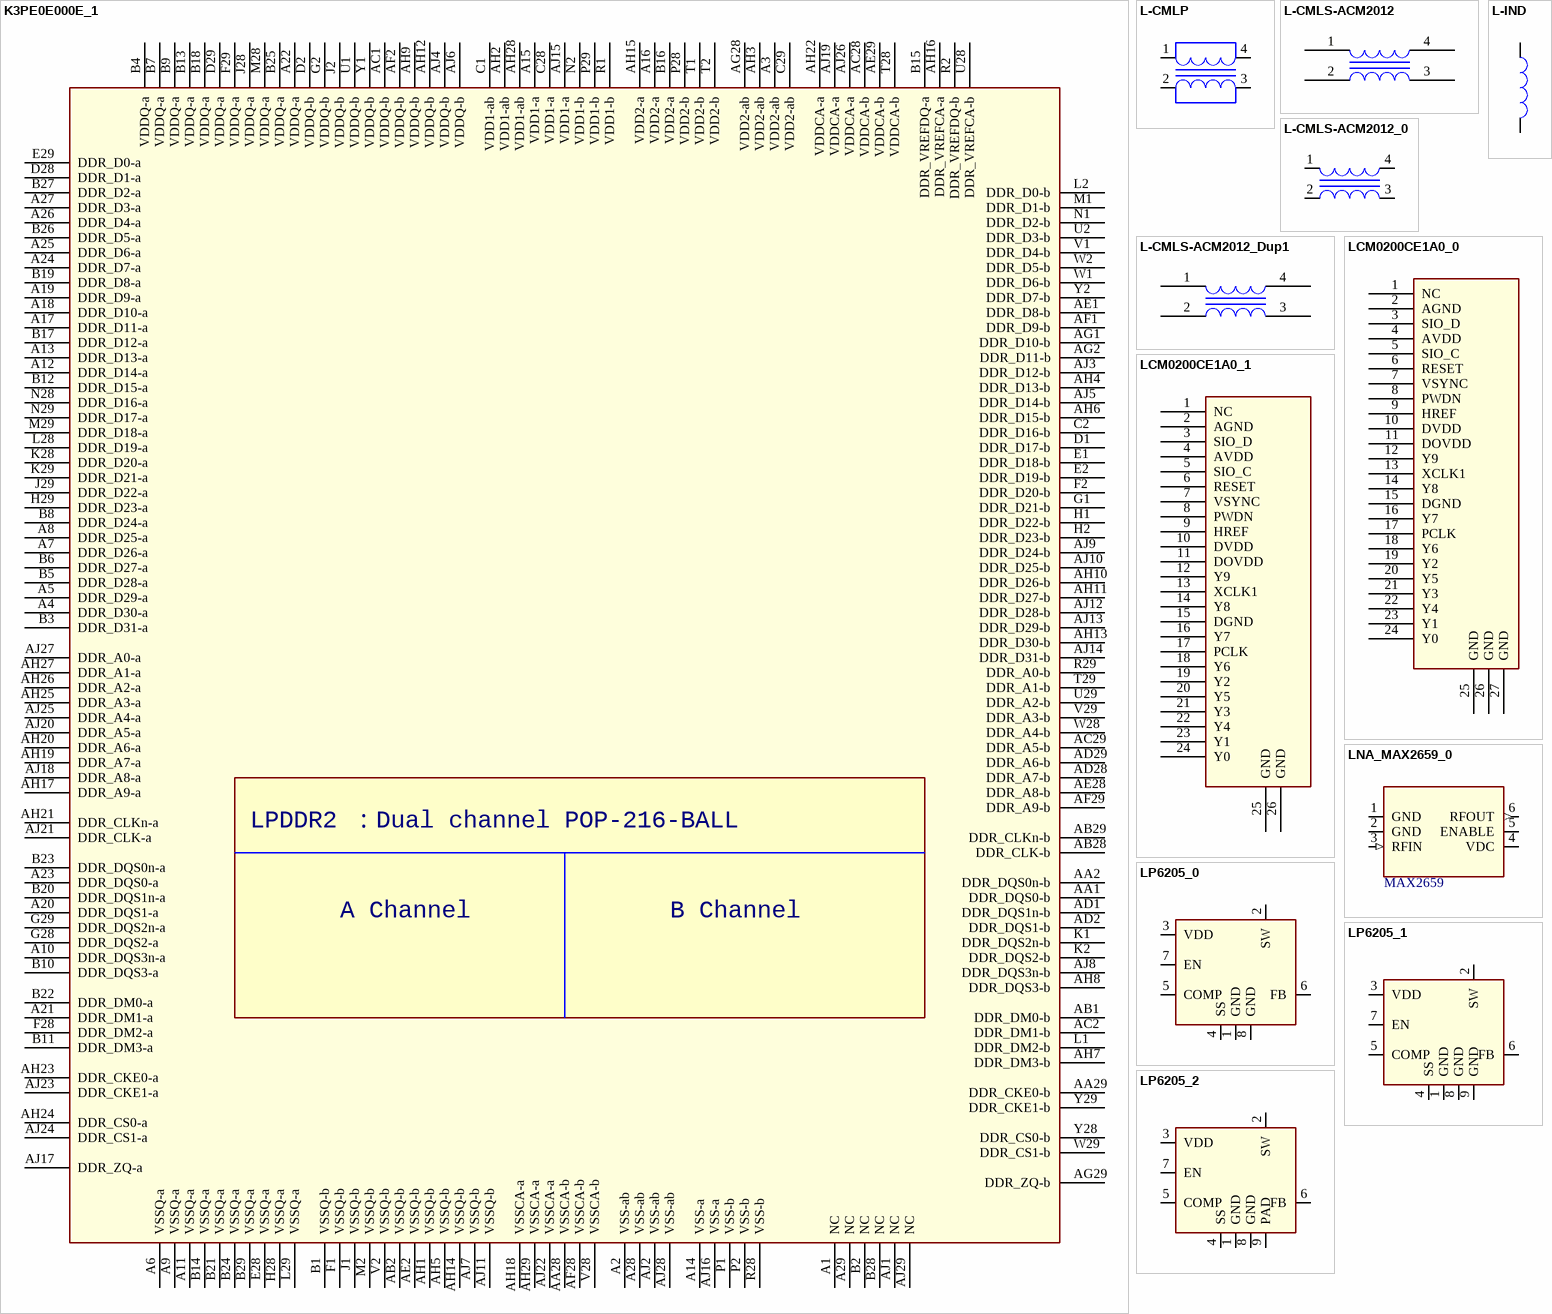
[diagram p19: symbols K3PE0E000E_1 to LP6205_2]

## K3PE0E000E_1
designator U?
Altium-Right: 660; Altium-Bottom: 770
footprint FBGA220-14X14
pins: A1 NC, A2 VSS-ab, A3 VDD2-ab, A4 DDR_D30-a, A5 DDR_D29-a, A6 VSSQ-a, A7 DDR_D26-a, A8 DDR_D25-a, A9 VSSQ-a, A10 DDR_DQS3n-a, A11 VSSQ-a, A12 DDR_D14-a, A13 DDR_D13-a, A14 VSS-a, A15 VDD1-a, A16 VDD2-a, A17 DDR_D11-a, A18 DDR_D10-a, A19 DDR_D9-a, A20 DDR_DQS1-a, A21 DDR_DM1-a, A22 VDDQ-a, A23 DDR_DQS0-a, A24 DDR_D7-a, A25 DDR_D6-a, A26 DDR_D4-a, A27 DDR_D3-a, A28 VSS-ab, A29 NC, AA1 DDR_DQS0-b, AA2 DDR_DQS0n-b, AA28 VSSCA-b, AA29 DDR_CKE0-b, AB1 DDR_DM0-b, AB2 VSSQ-b, AB28 DDR_CLK-b, AB29 DDR_CLKn-b, AC1 VDDQ-b, AC2 DDR_DM1-b, AC28 VDDCA-b, AC29 DDR_A5-b, AD1 DDR_DQS1n-b, AD2 DDR_DQS1-b, AD28 DDR_A7-b, AD29 DDR_A6-b, AE1 DDR_D8-b, AE2 VSSQ-b, AE28 DDR_A8-b, AE29 VDDCA-b, AF1 DDR_D9-b, AF2 VDDQ-b, AF28 VSSCA-b, AF29 DDR_A9-b, AG1 DDR_D10-b, AG2 DDR_D11-b, AG28 VDD2-ab, AG29 DDR_ZQ-b, AH1 VSSQ-b, AH2 VDD1-ab, AH3 VDD2-ab, AH4 DDR_D13-b, AH5 VSSQ-b, AH6 DDR_D15-b, AH7 DDR_DM3-b, AH8 DDR_DQS3-b, AH9 VDDQ-b, AH10 DDR_D26-b, AH11 DDR_D27-b, AH12 VDDQ-b, AH13 DDR_D30-b, AH14 VSSQ-b, AH15 VDD2-a, AH16 DDR_VREFCA-a, AH17 DDR_A9-a, AH18 VSSCA-a, AH19 DDR_A7-a, AH20 DDR_A6-a, AH21 DDR_CLKn-a, AH22 VDDCA-a, AH23 DDR_CKE0-a, AH24 DDR_CS0-a, AH25 DDR_A3-a, AH26 DDR_A2-a, AH27 DDR_A1-a, AH28 VDD1-ab, AH29 VSSCA-a, AJ1 NC, AJ2 VSS-ab, AJ3 DDR_D12-b, AJ4 VDDQ-b, AJ5 DDR_D14-b, AJ6 VDDQ-b, AJ7 VSSQ-b, AJ8 DDR_DQS3n-b, AJ9 DDR_D24-b, AJ10 DDR_D25-b, AJ11 VSSQ-b, AJ12 DDR_D28-b, AJ13 DDR_D29-b, AJ14 DDR_D31-b, AJ15 VDD1-a, AJ16 VSS-a, AJ17 DDR_ZQ-a, AJ18 DDR_A8-a, AJ19 VDDCA-a, AJ20 DDR_A5-a, AJ21 DDR_CLK-a, AJ22 VSSCA-a, AJ23 DDR_CKE1-a, AJ24 DDR_CS1-a, AJ25 DDR_A4-a, AJ26 VDDCA-a, AJ27 DDR_A0-a, AJ28 VSS-ab, AJ29 NC, B1 VSSQ-b, B2 NC, B3 DDR_D31-a, B4 VDDQ-a, B5 DDR_D28-a, B6 DDR_D27-a, B7 VDDQ-a, B8 DDR_D24-a, B9 VDDQ-a, B10 DDR_DQS3-a, B11 DDR_DM3-a, B12 DDR_D15-a, B13 VDDQ-a, B14 VSSQ-a, B15 DDR_VREFDQ-a, B16 VDD2-a, B17 DDR_D12-a, B18 VDDQ-a, B19 DDR_D8-a, B20 DDR_DQS1n-a, B21 VSSQ-a, B22 DDR_DM0-a, B23 DDR_DQS0n-a, B24 VSSQ-a, B25 VDDQ-a, B26 DDR_D5-a, B27 DDR_D2-a, B28 NC, B29 VSSQ-a, C1 VDD1-ab, C2 DDR_D16-b, C28 VDD1-a, C29 VDD2-ab, D1 DDR_D17-b, D2 VDDQ-b, D28 DDR_D1-a, D29 VDDQ-a, E1 DDR_D18-b, E2 DDR_D19-b, E28 VSSQ-a, E29 DDR_D0-a, F1 VSSQ-b, F2 DDR_D20-b, F28 DDR_DM2-a, F29 VDDQ-a, G1 DDR_D21-b, G2 VDDQ-b, G28 DDR_DQS2-a, G29 DDR_DQS2n-a, H1 DDR_D22-b, H2 DDR_D23-b, H28 VSSQ-a, H29 DDR_D23-a, J1 VSSQ-b, J2 VDDQ-b, J28 VDDQ-a, J29 DDR_D22-a, K1 DDR_DQS2n-b, K2 DDR_DQS2-b, K28 DDR_D20-a, K29 DDR_D21-a, L1 DDR_DM2-b, L2 DDR_D0-b, L28 DDR_D19-a, L29 VSSQ-a, M1 DDR_D1-b, M2 VSSQ-b, M28 VDDQ-a, M29 DDR_D18-a, N1 DDR_D2-b, N2 VDD1-b, N28 DDR_D16-a, N29 DDR_D17-a, P1 VSS-b, P2 VSS-b, P28 VDD2-b, P29 VDD1-b, R1 VDD1-b, R2 DDR_VREFDQ-b, R28 VSS-b, R29 DDR_A0-b, T1 VDD2-b, T2 VDD2-b, T28 VDDCA-b, T29 DDR_A1-b, U1 VDDQ-b, U2 DDR_D3-b, U28 DDR_VREFCA-b, U29 DDR_A2-b, V1 DDR_D4-b, V2 VSSQ-b, V28 VSSCA-b, V29 DDR_A3-b, W1 DDR_D6-b, W2 DDR_D5-b, W28 DDR_A4-b, W29 DDR_CS1-b, Y1 VDDQ-b, Y2 DDR_D7-b, Y28 DDR_CS0-b, Y29 DDR_CKE1-b

## L-CMLP
designator CMLP?
Altium-Right: 40
pins: 1, 2, 3, 4

## L-CMLS-ACM2012
designator CMLP?
Altium-Right: 40; Altium-Bottom: 20
pins: 1, 2, 3, 4

## L-CMLS-ACM2012_0
designator CMLP?
Altium-Right: 40; Altium-Bottom: 20
pins: 1, 2, 3, 4

## L-CMLS-ACM2012_Dup1
designator CMLP?
Altium-Right: 40; Altium-Bottom: 20
pins: 1, 2, 3, 4

## L-IND
designator L?
Altium-Right: 10; Altium-Bottom: 40
pins: 1, 2

## LCM0200CE1A0_0
designator U?
Altium-Right: 70; Altium-Bottom: 260
pins: 1 NC, 2 AGND, 3 SIO_D, 4 AVDD, 5 SIO_C, 6 RESET, 7 VSYNC, 8 PWDN, 9 HREF, 10 DVDD, 11 DOVDD, 12 Y9, 13 XCLK1, 14 Y8, 15 DGND, 16 Y7, 17 PCLK, 18 Y6, 19 Y2, 20 Y5, 21 Y3, 22 Y4, 23 Y1, 24 Y0, 25 GND, 26 GND, 27 GND

## LCM0200CE1A0_1
designator U?
Altium-Right: 70; Altium-Bottom: 260
pins: 1 NC, 2 AGND, 3 SIO_D, 4 AVDD, 5 SIO_C, 6 RESET, 7 VSYNC, 8 PWDN, 9 HREF, 10 DVDD, 11 DOVDD, 12 Y9, 13 XCLK1, 14 Y8, 15 DGND, 16 Y7, 17 PCLK, 18 Y6, 19 Y2, 20 Y5, 21 Y3, 22 Y4, 23 Y1, 24 Y0, 25 GND, 26 GND

## LNA_MAX2659_0
designator U?, comment MAX2659
Altium-Right: 80; Altium-Bottom: 60
footprint P-TSLP-7-1
pins: 1 GND (power), 2 GND, 3 RFIN (in), 4 VDC (power), 5 ENABLE, 6 RFOUT (out)

## LP6205_0
designator U?
Altium-Right: 80; Altium-Bottom: 70
pins: 1 GND, 2 SW, 3 VDD, 4 SS, 5 COMP, 6 FB, 7 EN, 8 GND

## LP6205_1
designator U?
Altium-Right: 80; Altium-Bottom: 70
pins: 1 GND, 2 SW, 3 VDD, 4 SS, 5 COMP, 6 FB, 7 EN, 8 GND, 9 GND

## LP6205_2
designator U?
Altium-Right: 80; Altium-Bottom: 70
pins: 1 GND, 2 SW, 3 VDD, 4 SS, 5 COMP, 6 FB, 7 EN, 8 GND, 9 PAD

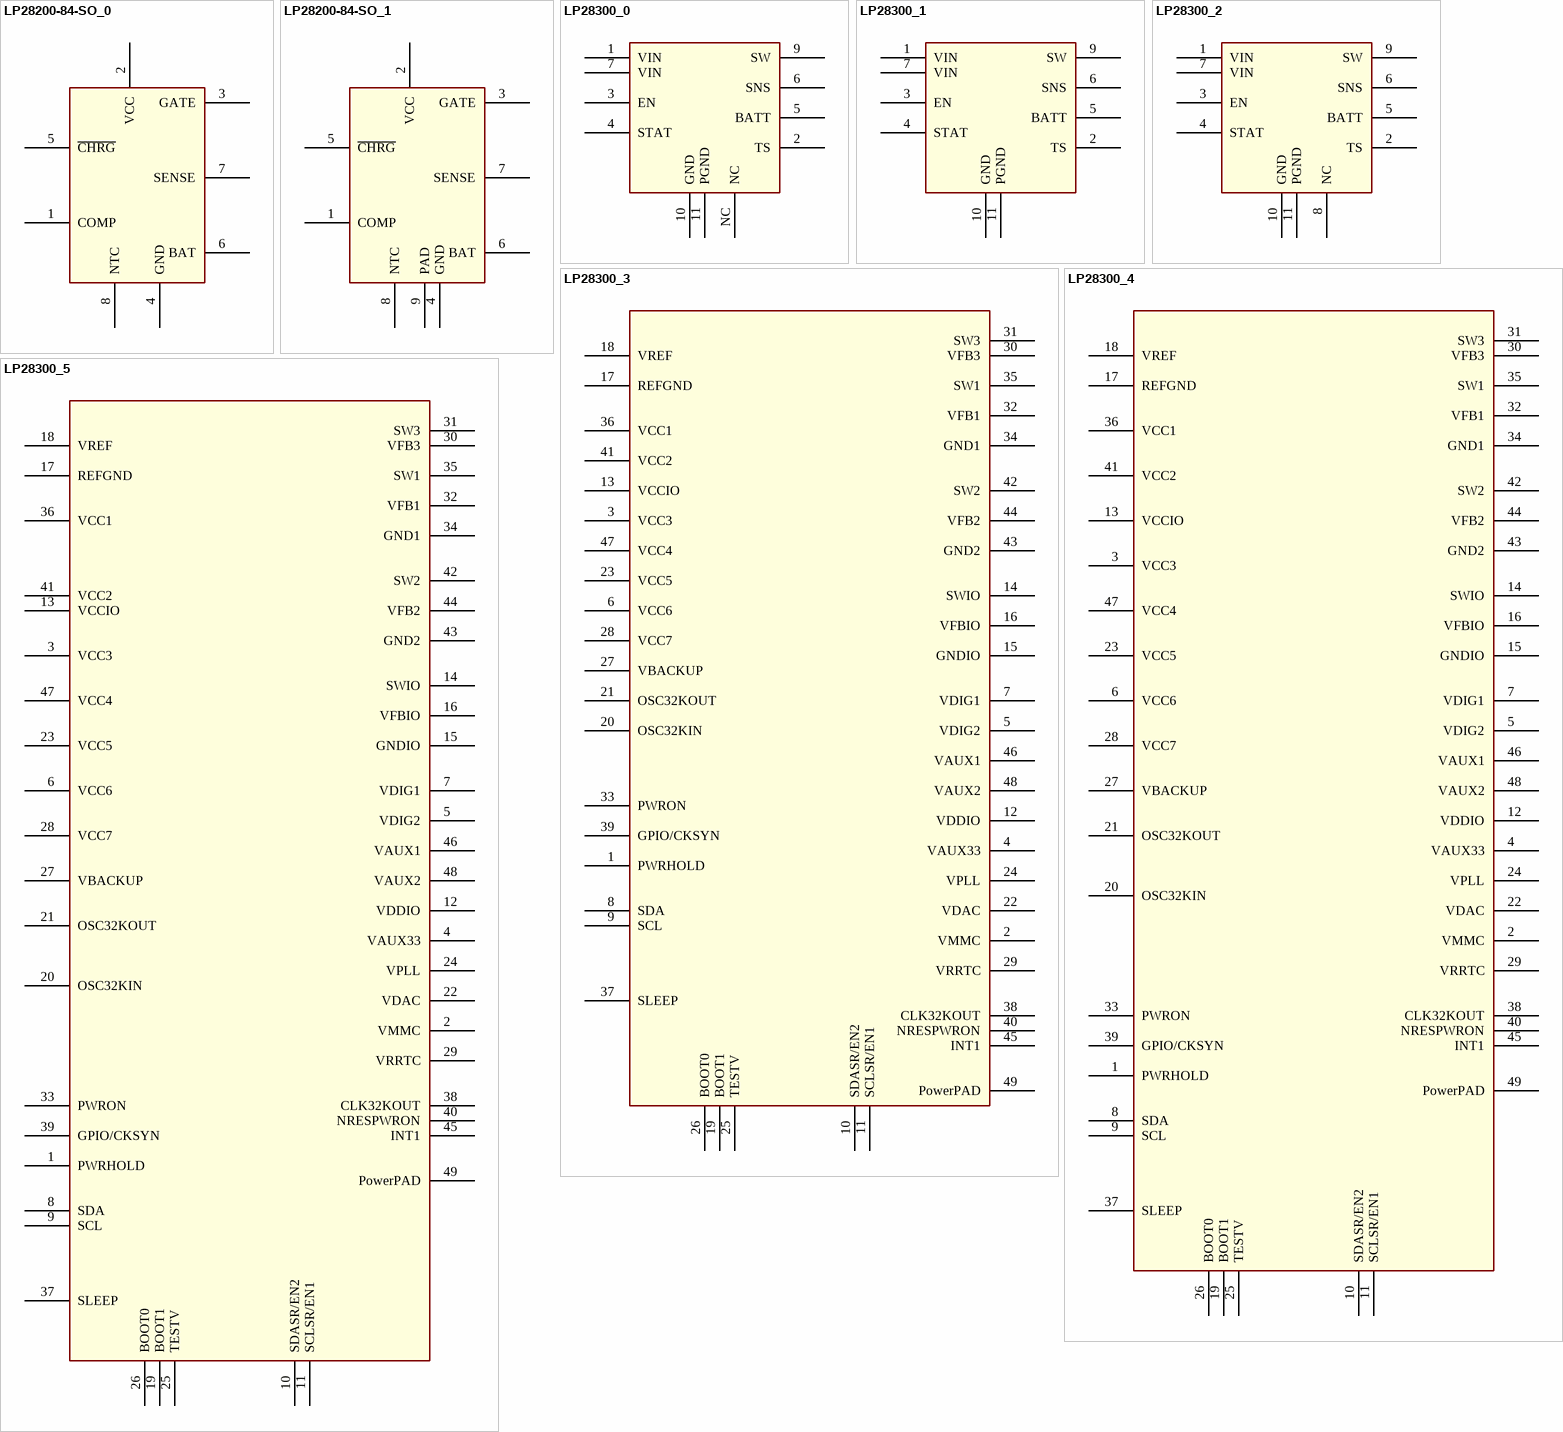
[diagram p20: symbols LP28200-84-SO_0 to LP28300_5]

## LP28200-84-SO_0
designator U?
Altium-Right: 90; Altium-Bottom: 130
footprint SOP8
pins: 1 COMP, 2 VCC, 3 GATE, 4 GND, 5 ~{CHRG}, 6 BAT, 7 SENSE, 8 NTC

## LP28200-84-SO_1
designator U?
Altium-Right: 90; Altium-Bottom: 130
footprint SOP8
pins: 1 COMP, 2 VCC, 3 GATE, 4 GND, 5 ~{CHRG}, 6 BAT, 7 SENSE, 8 NTC, 9 PAD

## LP28300_0
designator U?
Altium-Right: 100
footprint TDFN10
pins: 1 VIN, 2 TS, 3 EN, 4 STAT, 5 BATT, 6 SNS, 7 VIN, 9 SW, 10 GND, 11 PGND, NC

## LP28300_1
designator U?
Altium-Right: 100
footprint TDFN10
pins: 1 VIN, 2 TS, 3 EN, 4 STAT, 5 BATT, 6 SNS, 7 VIN, 9 SW, 10 GND, 11 PGND

## LP28300_2
designator U?
Altium-Right: 100
footprint TDFN10
pins: 1 VIN, 2 TS, 3 EN, 4 STAT, 5 BATT, 6 SNS, 7 VIN, 8 NC, 9 SW, 10 GND, 11 PGND

## LP28300_3
designator U?
Altium-Right: 240; Altium-Bottom: 530
footprint TDFN10
pins: 1 PWRHOLD, 2 VMMC, 3 VCC3, 4 VAUX33, 5 VDIG2, 6 VCC6, 7 VDIG1, 8 SDA, 9 SCL, 10 SDASR/EN2, 11 SCLSR/EN1, 12 VDDIO, 13 VCCIO, 14 SWIO, 15 GNDIO, 16 VFBIO, 17 REFGND, 18 VREF, 19 BOOT1, 20 OSC32KIN, 21 OSC32KOUT, 22 VDAC, 23 VCC5, 24 VPLL, 25 TESTV, 26 BOOT0, 27 VBACKUP, 28 VCC7, 29 VRRTC, 30 VFB3, 31 SW3, 32 VFB1, 33 PWRON, 34 GND1, 35 SW1, 36 VCC1, 37 SLEEP, 38 CLK32KOUT, 39 GPIO/CKSYN, 40 NRESPWRON, 41 VCC2, 42 SW2, 43 GND2, 44 VFB2, 45 INT1, 46 VAUX1, 47 VCC4, 48 VAUX2, 49 PowerPAD

## LP28300_4
designator U?
Altium-Right: 240; Altium-Bottom: 640
footprint TDFN10
pins: 1 PWRHOLD, 2 VMMC, 3 VCC3, 4 VAUX33, 5 VDIG2, 6 VCC6, 7 VDIG1, 8 SDA, 9 SCL, 10 SDASR/EN2, 11 SCLSR/EN1, 12 VDDIO, 13 VCCIO, 14 SWIO, 15 GNDIO, 16 VFBIO, 17 REFGND, 18 VREF, 19 BOOT1, 20 OSC32KIN, 21 OSC32KOUT, 22 VDAC, 23 VCC5, 24 VPLL, 25 TESTV, 26 BOOT0, 27 VBACKUP, 28 VCC7, 29 VRRTC, 30 VFB3, 31 SW3, 32 VFB1, 33 PWRON, 34 GND1, 35 SW1, 36 VCC1, 37 SLEEP, 38 CLK32KOUT, 39 GPIO/CKSYN, 40 NRESPWRON, 41 VCC2, 42 SW2, 43 GND2, 44 VFB2, 45 INT1, 46 VAUX1, 47 VCC4, 48 VAUX2, 49 PowerPAD

## LP28300_5
designator U?
Altium-Right: 240; Altium-Bottom: 640
footprint TDFN10
pins: 1 PWRHOLD, 2 VMMC, 3 VCC3, 4 VAUX33, 5 VDIG2, 6 VCC6, 7 VDIG1, 8 SDA, 9 SCL, 10 SDASR/EN2, 11 SCLSR/EN1, 12 VDDIO, 13 VCCIO, 14 SWIO, 15 GNDIO, 16 VFBIO, 17 REFGND, 18 VREF, 19 BOOT1, 20 OSC32KIN, 21 OSC32KOUT, 22 VDAC, 23 VCC5, 24 VPLL, 25 TESTV, 26 BOOT0, 27 VBACKUP, 28 VCC7, 29 VRRTC, 30 VFB3, 31 SW3, 32 VFB1, 33 PWRON, 34 GND1, 35 SW1, 36 VCC1, 37 SLEEP, 38 CLK32KOUT, 39 GPIO/CKSYN, 40 NRESPWRON, 41 VCC2, 42 SW2, 43 GND2, 44 VFB2, 45 INT1, 46 VAUX1, 47 VCC4, 48 VAUX2, 49 PowerPAD

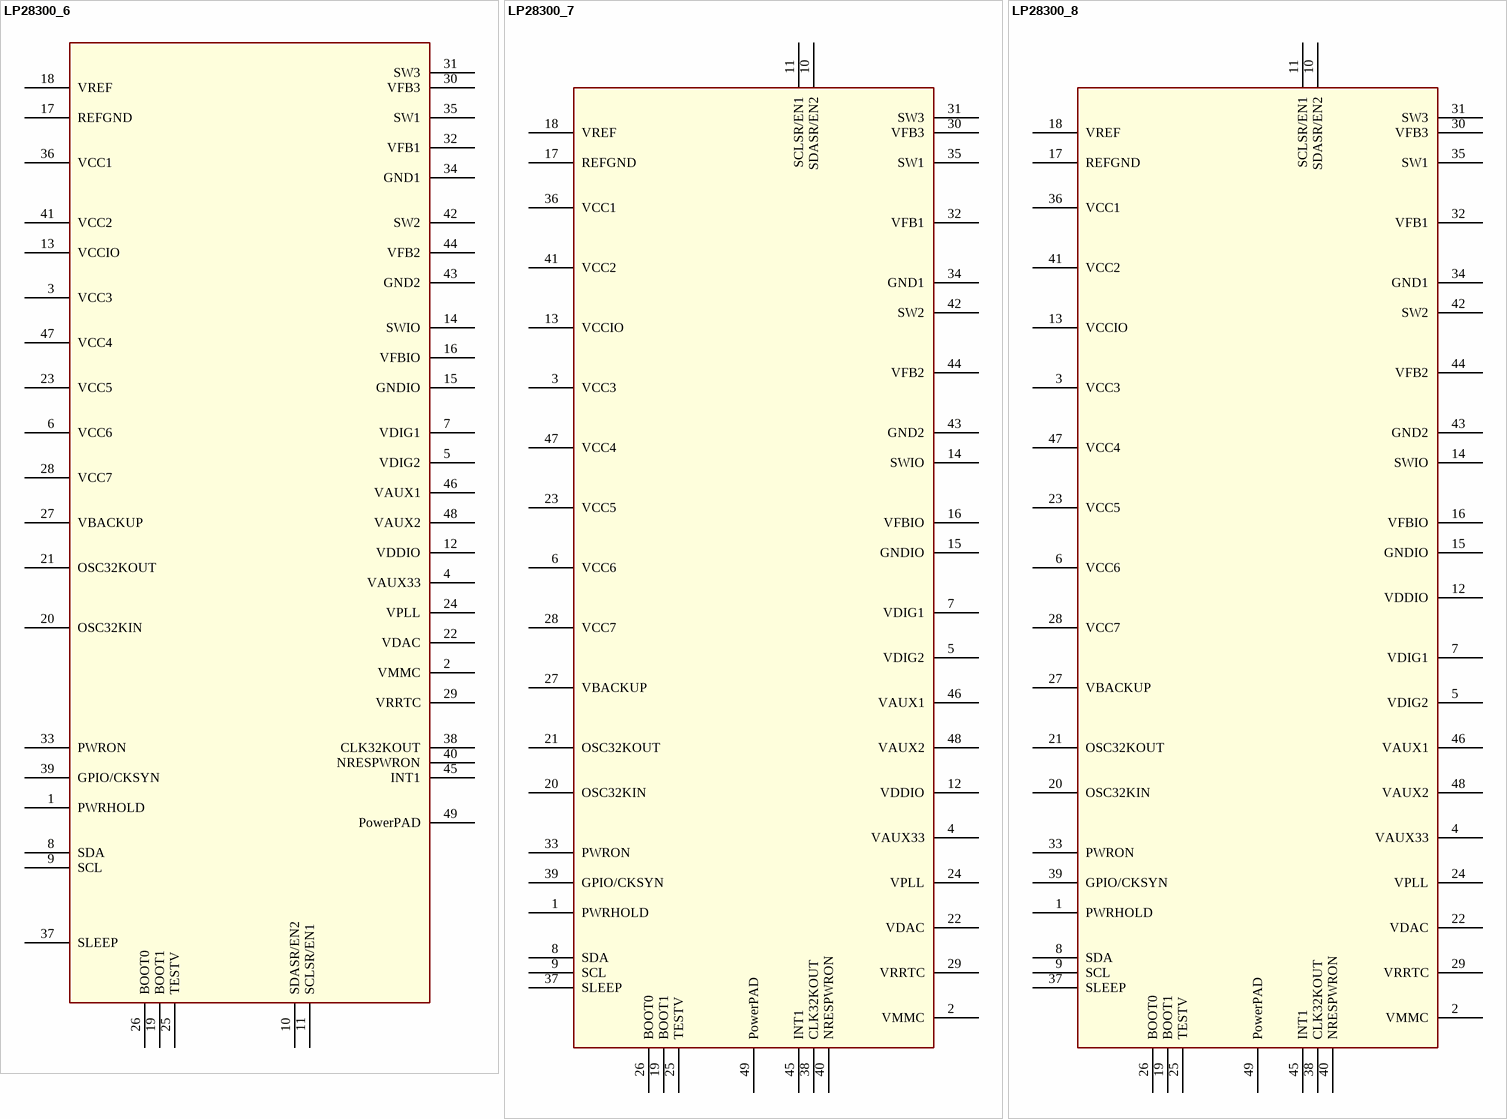
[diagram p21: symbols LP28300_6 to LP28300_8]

## LP28300_6
designator U?
Altium-Right: 240; Altium-Bottom: 640
footprint TDFN10
pins: 1 PWRHOLD, 2 VMMC, 3 VCC3, 4 VAUX33, 5 VDIG2, 6 VCC6, 7 VDIG1, 8 SDA, 9 SCL, 10 SDASR/EN2, 11 SCLSR/EN1, 12 VDDIO, 13 VCCIO, 14 SWIO, 15 GNDIO, 16 VFBIO, 17 REFGND, 18 VREF, 19 BOOT1, 20 OSC32KIN, 21 OSC32KOUT, 22 VDAC, 23 VCC5, 24 VPLL, 25 TESTV, 26 BOOT0, 27 VBACKUP, 28 VCC7, 29 VRRTC, 30 VFB3, 31 SW3, 32 VFB1, 33 PWRON, 34 GND1, 35 SW1, 36 VCC1, 37 SLEEP, 38 CLK32KOUT, 39 GPIO/CKSYN, 40 NRESPWRON, 41 VCC2, 42 SW2, 43 GND2, 44 VFB2, 45 INT1, 46 VAUX1, 47 VCC4, 48 VAUX2, 49 PowerPAD

## LP28300_7
designator U?
Altium-Right: 240; Altium-Bottom: 640
footprint TDFN10
pins: 1 PWRHOLD, 2 VMMC, 3 VCC3, 4 VAUX33, 5 VDIG2, 6 VCC6, 7 VDIG1, 8 SDA, 9 SCL, 10 SDASR/EN2, 11 SCLSR/EN1, 12 VDDIO, 13 VCCIO, 14 SWIO, 15 GNDIO, 16 VFBIO, 17 REFGND, 18 VREF, 19 BOOT1, 20 OSC32KIN, 21 OSC32KOUT, 22 VDAC, 23 VCC5, 24 VPLL, 25 TESTV, 26 BOOT0, 27 VBACKUP, 28 VCC7, 29 VRRTC, 30 VFB3, 31 SW3, 32 VFB1, 33 PWRON, 34 GND1, 35 SW1, 36 VCC1, 37 SLEEP, 38 CLK32KOUT, 39 GPIO/CKSYN, 40 NRESPWRON, 41 VCC2, 42 SW2, 43 GND2, 44 VFB2, 45 INT1, 46 VAUX1, 47 VCC4, 48 VAUX2, 49 PowerPAD

## LP28300_8
designator U?
Altium-Right: 240; Altium-Bottom: 640
footprint TDFN10
pins: 1 PWRHOLD, 2 VMMC, 3 VCC3, 4 VAUX33, 5 VDIG2, 6 VCC6, 7 VDIG1, 8 SDA, 9 SCL, 10 SDASR/EN2, 11 SCLSR/EN1, 12 VDDIO, 13 VCCIO, 14 SWIO, 15 GNDIO, 16 VFBIO, 17 REFGND, 18 VREF, 19 BOOT1, 20 OSC32KIN, 21 OSC32KOUT, 22 VDAC, 23 VCC5, 24 VPLL, 25 TESTV, 26 BOOT0, 27 VBACKUP, 28 VCC7, 29 VRRTC, 30 VFB3, 31 SW3, 32 VFB1, 33 PWRON, 34 GND1, 35 SW1, 36 VCC1, 37 SLEEP, 38 CLK32KOUT, 39 GPIO/CKSYN, 40 NRESPWRON, 41 VCC2, 42 SW2, 43 GND2, 44 VFB2, 45 INT1, 46 VAUX1, 47 VCC4, 48 VAUX2, 49 PowerPAD

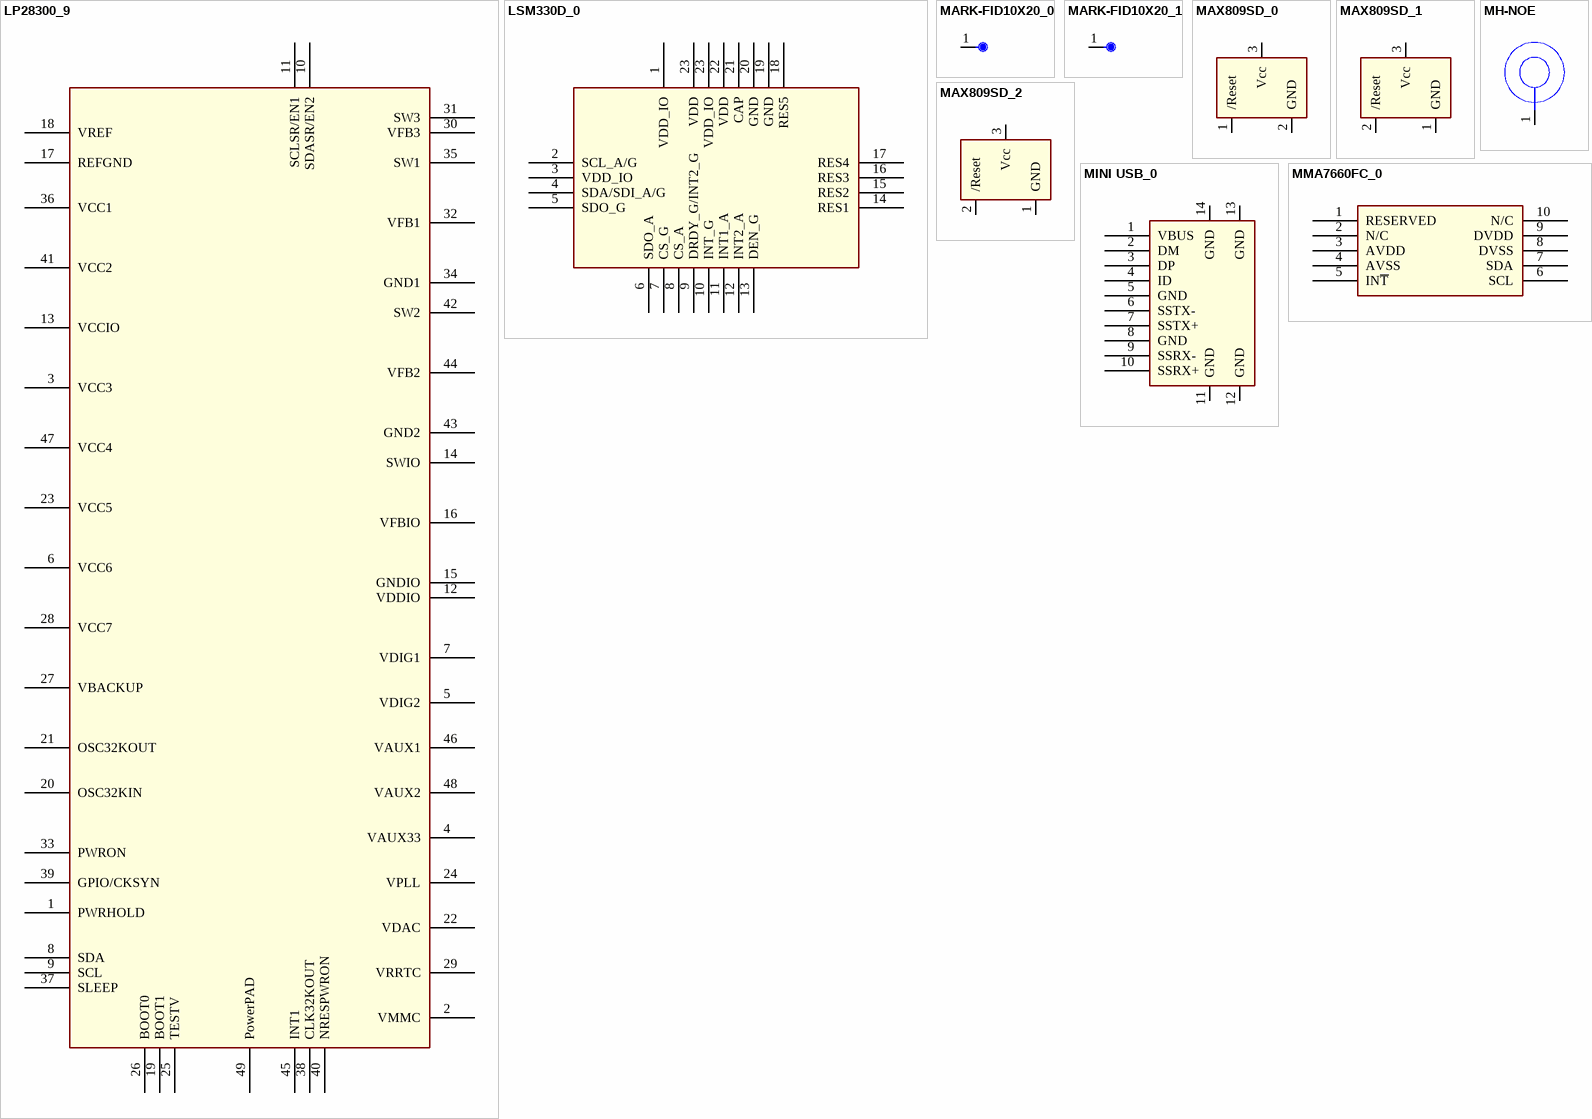
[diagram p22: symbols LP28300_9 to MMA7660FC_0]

## LP28300_9
designator U?
Altium-Right: 240; Altium-Bottom: 640
footprint TDFN10
pins: 1 PWRHOLD, 2 VMMC, 3 VCC3, 4 VAUX33, 5 VDIG2, 6 VCC6, 7 VDIG1, 8 SDA, 9 SCL, 10 SDASR/EN2, 11 SCLSR/EN1, 12 VDDIO, 13 VCCIO, 14 SWIO, 15 GNDIO, 16 VFBIO, 17 REFGND, 18 VREF, 19 BOOT1, 20 OSC32KIN, 21 OSC32KOUT, 22 VDAC, 23 VCC5, 24 VPLL, 25 TESTV, 26 BOOT0, 27 VBACKUP, 28 VCC7, 29 VRRTC, 30 VFB3, 31 SW3, 32 VFB1, 33 PWRON, 34 GND1, 35 SW1, 36 VCC1, 37 SLEEP, 38 CLK32KOUT, 39 GPIO/CKSYN, 40 NRESPWRON, 41 VCC2, 42 SW2, 43 GND2, 44 VFB2, 45 INT1, 46 VAUX1, 47 VCC4, 48 VAUX2, 49 PowerPAD

## LSM330D_0
designator U?
Altium-Right: 190; Altium-Bottom: 120
footprint L3G4200D
pins: 1 VDD_IO, 2 SCL_A/G, 3 VDD_IO, 4 SDA/SDI_A/G, 5 SDO_G, 6 SDO_A, 7 CS_G, 8 CS_A, 9 DRDY_G/INT2_G, 10 INT_G, 11 INT1_A, 12 INT2_A, 13 DEN_G, 14 RES1, 15 RES2, 16 RES3, 17 RES4, 18 RES5, 19 GND (power), 20 GND (power), 21 CAP, 22 VDD, 23 VDD, 23 VDD_IO

## MARK-FID10X20_0
designator TP?
Part Number: CAD; Altium-Right: 10; Altium-Bottom: 20
footprint E-Mark-TP-02-100x
pins: 1

## MARK-FID10X20_1
designator TP?
Part Number: CAD; Altium-Right: 10; Altium-Bottom: 20
footprint E-Mark-TP-02-100x
pins: 1

## MAX809SD_0
designator U?
Altium-Right: 60; Altium-Bottom: 40
pins: 1 /Reset, 2 GND, 3 Vcc

## MAX809SD_1
designator U?
Altium-Right: 60; Altium-Bottom: 40
pins: 1 GND, 2 /Reset, 3 Vcc

## MAX809SD_2
designator U?
Altium-Right: 60; Altium-Bottom: 40
pins: 1 GND, 2 /Reset, 3 Vcc

## MH-NOE
designator MH?
Part Number: CAD; Altium-Right: 40; Altium-Bottom: 50
footprint MH276_091
pins: 1

## MINI USB_0
designator U?
Altium-Right: 70; Altium-Bottom: 110
pins: 1 VBUS, 2 DM, 3 DP, 4 ID, 5 GND, 6 SSTX-, 7 SSTX+, 8 GND (power), 9 SSRX-, 10 SSRX+, 11 GND, 12 GND, 13 GND, 14 GND

## MMA7660FC_0
designator U?
Altium-Right: 110; Altium-Bottom: 60
pins: 1 RESERVED, 2 N/C, 3 AVDD, 4 AVSS, 5 IN~{T}, 6 SCL, 7 SDA, 8 DVSS, 9 DVDD, 10 N/C

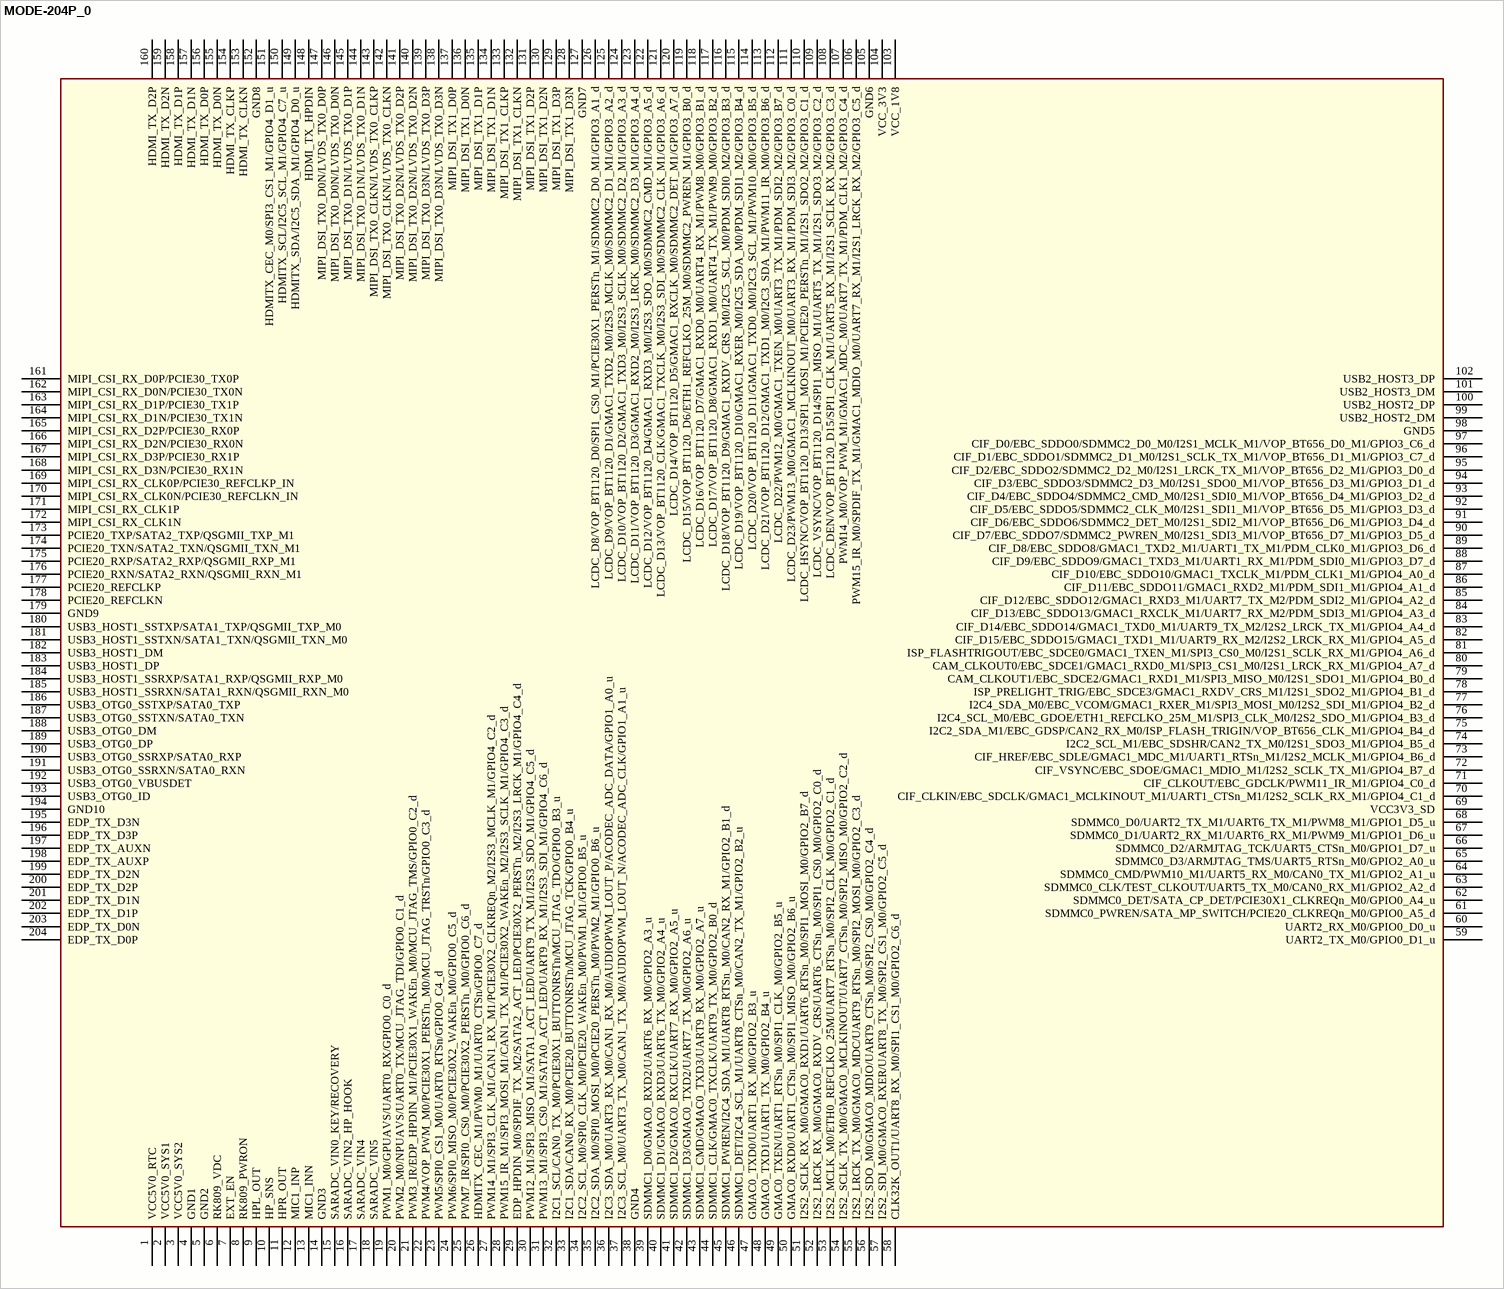
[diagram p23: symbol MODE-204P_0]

## MODE-204P_0
designator M?
Altium-Right: 1060; Altium-Bottom: 880
pins: 1 VCC5V0_RTC, 2 VCC5V0_SYS1, 3 VCC5V0_SYS2 (power), 4 GND1, 5 GND2, 6 RK809_VDC, 7 EXT_EN, 8 RK809_PWRON, 9 HPL_OUT, 10 HP_SNS, 11 HPR_OUT, 12 MIC1_INP, 13 MIC1_INN, 14 GND3, 15 SARADC_VIN0_KEY/RECOVERY, 16 SARADC_VIN2_HP_HOOK, 17 SARADC_VIN4, 18 SARADC_VIN5, 19 PWM1_M0/GPUAVS/UART0_RX/GPIO0_C0_d, 20 PWM2_M0/NPUAVS/UART0_TX/MCU_JTAG_TDI/GPIO0_C1_d, 21 PWM3_IR/EDP_HPDIN_M1/PCIE30X1_WAKEn_M0/MCU_JTAG_TMS/GPIO0_C2_d, 22 PWM4/VOP_PWM_M0/PCIE30X1_PERSTn_M0/MCU_JTAG_TRSTn/GPIO0_C3_d, 23 PWM5/SPI0_CS1_M0/UART0_RTSn/GPIO0_C4_d, 24 PWM6/SPI0_MISO_M0/PCIE30X2_WAKEn_M0/GPIO0_C5_d, 25 PWM7_IR/SPI0_CS0_M0/PCIE30X2_PERSTn_M0/GPIO0_C6_d, 26 HDMITX_CEC_M1/PWM0_M1/UART0_CTSn/GPIO0_C7_d (power), 27 PWM14_M1/SPI3_CLK_M1/CAN1_RX_M1/PCIE30X2_CLKREQn_M2/I2S3_MCLK_M1/GPIO4_C2_d, 28 PWM15_IR_M1/SPI3_MOSI_M1/CAN1_TX_M1/PCIE30X2_WAKEn_M2/I2S3_SCLK_M1/GPIO4_C3_d, 29 EDP_HPDIN_M0/SPDIF_TX_M2/SATA2_ACT_LED/PCIE30X2_PERSTn_M2/I2S3_LRCK_M1/GPIO4_C4_d, 30 PWM12_M1/SPI3_MISO_M1/SATA1_ACT_LED/UART9_TX_M1/I2S3_SDO_M1/GPIO4_C5_d, 31 PWM13_M1/SPI3_CS0_M1/SATA0_ACT_LED/UART9_RX_M1/I2S3_SDI_M1/GPIO4_C6_d, 32 I2C1_SCL/CAN0_TX_M0/PCIE30X1_BUTTONRSTn/MCU_JTAG_TDO/GPIO0_B3_u, 33 I2C1_SDA/CAN0_RX_M0/PCIE20_BUTTONRSTn/MCU_JTAG_TCK/GPIO0_B4_u, 34 I2C2_SCL_M0/SPI0_CLK_M0/PCIE20_WAKEn_M0/PWM1_M1/GPIO0_B5_u, 35 I2C2_SDA_M0/SPI0_MOSI_M0/PCIE20_PERSTn_M0/PWM2_M1/GPIO0_B6_u, 36 I2C3_SDA_M0/UART3_RX_M0/CAN1_RX_M0/AUDIOPWM_LOUT_P/ACODEC_ADC_DATA/GPIO1_A0_u, 37 I2C3_SCL_M0/UART3_TX_M0/CAN1_TX_M0/AUDIOPWM_LOUT_N/ACODEC_ADC_CLK/GPIO1_A1_u, 38 GND4, 39 SDMMC1_D0/GMAC0_RXD2/UART6_RX_M0/GPIO2_A3_u, 40 SDMMC1_D1/GMAC0_RXD3/UART6_TX_M0/GPIO2_A4_u, 41 SDMMC1_D2/GMAC0_RXCLK/UART7_RX_M0/GPIO2_A5_u, 42 SDMMC1_D3/GMAC0_TXD2/UART7_TX_M0/GPIO2_A6_u, 43 SDMMC1_CMD/GMAC0_TXD3/UART9_RX_M0/GPIO2_A7_u, 44 SDMMC1_CLK/GMAC0_TXCLK/UART9_TX_M0/GPIO2_B0_d, 45 SDMMC1_PWREN/I2C4_SDA_M1/UART8_RTSn_M0/CAN2_RX_M1/GPIO2_B1_d, 46 SDMMC1_DET/I2C4_SCL_M1/UART8_CTSn_M0/CAN2_TX_M1/GPIO2_B2_u, 47 GMAC0_TXD0/UART1_RX_M0/GPIO2_B3_u, 48 GMAC0_TXD1/UART1_TX_M0/GPIO2_B4_u (power), 49 GMAC0_TXEN/UART1_RTSn_M0/SPI1_CLK_M0/GPIO2_B5_u (power), 50 GMAC0_RXD0/UART1_CTSn_M0/SPI1_MISO_M0/GPIO2_B6_u, 51 I2S2_SCLK_RX_M0/GMAC0_RXD1/UART6_RTSn_M0/SPI1_MOSI_M0/GPIO2_B7_d, 52 I2S2_LRCK_RX_M0/GMAC0_RXDV_CRS/UART6_CTSn_M0/SPI1_CS0_M0/GPIO2_C0_d, 53 I2S2_MCLK_M0/ETH0_REFCLKO_25M/UART7_RTSn_M0/SPI2_CLK_M0/GPIO2_C1_d, 54 I2S2_SCLK_TX_M0/GMAC0_MCLKINOUT/UART7_CTSn_M0/SPI2_MISO_M0/GPIO2_C2_d, 55 I2S2_LRCK_TX_M0/GMAC0_MDC/UART9_RTSn_M0/SPI2_MOSI_M0/GPIO2_C3_d, 56 I2S2_SDO_M0/GMAC0_MDIO/UART9_CTSn_M0/SPI2_CS0_M0/GPIO2_C4_d, 57 I2S2_SDI_M0/GMAC0_RXER/UART8_TX_M0/SPI2_CS1_M0/GPIO2_C5_d, 58 CLK32K_OUT1/UART8_RX_M0/SPI1_CS1_M0/GPIO2_C6_d, 59 UART2_TX_M0/GPIO0_D1_u, 60 UART2_RX_M0/GPIO0_D0_u, 61 SDMMC0_PWREN/SATA_MP_SWITCH/PCIE20_CLKREQn_M0/GPIO0_A5_d, 62 SDMMC0_DET/SATA_CP_DET/PCIE30X1_CLKREQn_M0/GPIO0_A4_u, 63 SDMMC0_CLK/TEST_CLKOUT/UART5_TX_M0/CAN0_RX_M1/GPIO2_A2_d, 64 SDMMC0_CMD/PWM10_M1/UART5_RX_M0/CAN0_TX_M1/GPIO2_A1_u (power), 65 SDMMC0_D3/ARMJTAG_TMS/UART5_RTSn_M0/GPIO2_A0_u, 66 SDMMC0_D2/ARMJTAG_TCK/UART5_CTSn_M0/GPIO1_D7_u, 67 SDMMC0_D1/UART2_RX_M1/UART6_RX_M1/PWM9_M1/GPIO1_D6_u, 68 SDMMC0_D0/UART2_TX_M1/UART6_TX_M1/PWM8_M1/GPIO1_D5_u, 69 VCC3V3_SD, 70 CIF_CLKIN/EBC_SDCLK/GMAC1_MCLKINOUT_M1/UART1_CTSn_M1/I2S2_SCLK_RX_M1/GPIO4_C1_d, 71 CIF_CLKOUT/EBC_GDCLK/PWM11_IR_M1/GPIO4_C0_d, 72 CIF_VSYNC/EBC_SDOE/GMAC1_MDIO_M1/I2S2_SCLK_TX_M1/GPIO4_B7_d, 73 CIF_HREF/EBC_SDLE/GMAC1_MDC_M1/UART1_RTSn_M1/I2S2_MCLK_M1/GPIO4_B6_d, 74 I2C2_SCL_M1/EBC_SDSHR/CAN2_TX_M0/I2S1_SDO3_M1/GPIO4_B5_d, 75 I2C2_SDA_M1/EBC_GDSP/CAN2_RX_M0/ISP_FLASH_TRIGIN/VOP_BT656_CLK_M1/GPIO4_B4_d, 76 I2C4_SCL_M0/EBC_GDOE/ETH1_REFCLKO_25M_M1/SPI3_CLK_M0/I2S2_SDO_M1/GPIO4_B3_d, 77 I2C4_SDA_M0/EBC_VCOM/GMAC1_RXER_M1/SPI3_MOSI_M0/I2S2_SDI_M1/GPIO4_B2_d, 78 ISP_PRELIGHT_TRIG/EBC_SDCE3/GMAC1_RXDV_CRS_M1/I2S1_SDO2_M1/GPIO4_B1_d (power), 79 CAM_CLKOUT1/EBC_SDCE2/GMAC1_RXD1_M1/SPI3_MISO_M0/I2S1_SDO1_M1/GPIO4_B0_d, 80 CAM_CLKOUT0/EBC_SDCE1/GMAC1_RXD0_M1/SPI3_CS1_M0/I2S1_LRCK_RX_M1/GPIO4_A7_d, 81 ISP_FLASHTRIGOUT/EBC_SDCE0/GMAC1_TXEN_M1/SPI3_CS0_M0/I2S1_SCLK_RX_M1/GPIO4_A6_d, 82 CIF_D15/EBC_SDDO15/GMAC1_TXD1_M1/UART9_RX_M2/I2S2_LRCK_RX_M1/GPIO4_A5_d, 83 CIF_D14/EBC_SDDO14/GMAC1_TXD0_M1/UART9_TX_M2/I2S2_LRCK_TX_M1/GPIO4_A4_d, 84 CIF_D13/EBC_SDDO13/GMAC1_RXCLK_M1/UART7_RX_M2/PDM_SDI3_M1/GPIO4_A3_d, 85 CIF_D12/EBC_SDDO12/GMAC1_RXD3_M1/UART7_TX_M2/PDM_SDI2_M1/GPIO4_A2_d, 86 CIF_D11/EBC_SDDO11/GMAC1_RXD2_M1/PDM_SDI1_M1/GPIO4_A1_d, 87 CIF_D10/EBC_SDDO10/GMAC1_TXCLK_M1/PDM_CLK1_M1/GPIO4_A0_d, 88 CIF_D9/EBC_SDDO9/GMAC1_TXD3_M1/UART1_RX_M1/PDM_SDI0_M1/GPIO3_D7_d, 89 CIF_D8/EBC_SDDO8/GMAC1_TXD2_M1/UART1_TX_M1/PDM_CLK0_M1/GPIO3_D6_d, 90 CIF_D7/EBC_SDDO7/SDMMC2_PWREN_M0/I2S1_SDI3_M1/VOP_BT656_D7_M1/GPIO3_D5_d, 91 CIF_D6/EBC_SDDO6/SDMMC2_DET_M0/I2S1_SDI2_M1/VOP_BT656_D6_M1/GPIO3_D4_d, 92 CIF_D5/EBC_SDDO5/SDMMC2_CLK_M0/I2S1_SDI1_M1/VOP_BT656_D5_M1/GPIO3_D3_d, 93 CIF_D4/EBC_SDDO4/SDMMC2_CMD_M0/I2S1_SDI0_M1/VOP_BT656_D4_M1/GPIO3_D2_d, 94 CIF_D3/EBC_SDDO3/SDMMC2_D3_M0/I2S1_SDO0_M1/VOP_BT656_D3_M1/GPIO3_D1_d, 95 CIF_D2/EBC_SDDO2/SDMMC2_D2_M0/I2S1_LRCK_TX_M1/VOP_BT656_D2_M1/GPIO3_D0_d, 96 CIF_D1/EBC_SDDO1/SDMMC2_D1_M0/I2S1_SCLK_TX_M1/VOP_BT656_D1_M1/GPIO3_C7_d, 97 CIF_D0/EBC_SDDO0/SDMMC2_D0_M0/I2S1_MCLK_M1/VOP_BT656_D0_M1/GPIO3_C6_d, 98 GND5, 99 USB2_HOST2_DM, 100 USB2_HOST2_DP, 101 USB2_HOST3_DM (power), 102 USB2_HOST3_DP, 103 VCC_1V8, 104 VCC_3V3, 105 GND6, 106 PWM15_IR_M0/SPDIF_TX_M1/GMAC1_MDIO_M0/UART7_RX_M1/I2S1_LRCK_RX_M2/GPIO3_C5_d, 107 PWM14_M0/VOP_PWM_M1/GMAC1_MDC_M0/UART7_TX_M1/PDM_CLK1_M2/GPIO3_C4_d, 108 LCDC_DEN/VOP_BT1120_D15/SPI1_CLK_M1/UART5_RX_M1/I2S1_SCLK_RX_M2/GPIO3_C3_d, 109 LCDC_VSYNC/VOP_BT1120_D14/SPI1_MISO_M1/UART5_TX_M1/I2S1_SDO3_M2/GPIO3_C2_d, 110 LCDC_HSYNC/VOP_BT1120_D13/SPI1_MOSI_M1/PCIE20_PERSTn_M1/I2S1_SDO2_M2/GPIO3_C1_d, 111 LCDC_D23/PWM13_M0/GMAC1_MCLKINOUT_M0/UART3_RX_M1/PDM_SDI3_M2/GPIO3_C0_d, 112 LCDC_D22/PWM12_M0/GMAC1_TXEN_M0/UART3_TX_M1/PDM_SDI2_M2/GPIO3_B7_d, 113 LCDC_D21/VOP_BT1120_D12/GMAC1_TXD1_M0/I2C3_SDA_M1/PWM11_IR_M0/GPIO3_B6_d, 114 LCDC_D20/VOP_BT1120_D11/GMAC1_TXD0_M0/I2C3_SCL_M1/PWM10_M0/GPIO3_B5_d, 115 LCDC_D19/VOP_BT1120_D10/GMAC1_RXER_M0/I2C5_SDA_M0/PDM_SDI1_M2/GPIO3_B4_d, 116 LCDC_D18/VOP_BT1120_D9/GMAC1_RXDV_CRS_M0/I2C5_SCL_M0/PDM_SDI0_M2/GPIO3_B3_d, 117 LCDC_D17/VOP_BT1120_D8/GMAC1_RXD1_M0/UART4_TX_M1/PWM9_M0/GPIO3_B2_d, 118 LCDC_D16/VOP_BT1120_D7/GMAC1_RXD0_M0/UART4_RX_M1/PWM8_M0/GPIO3_B1_d, 119 LCDC_D15/VOP_BT1120_D6/ETH1_REFCLKO_25M_M0/SDMMC2_PWREN_M1/GPIO3_B0_d, 120 LCDC_D14/VOP_BT1120_D5/GMAC1_RXCLK_M0/SDMMC2_DET_M1/GPIO3_A7_d, 121 LCDC_D13/VOP_BT1120_CLK/GMAC1_TXCLK_M0/I2S3_SDI_M0/SDMMC2_CLK_M1/GPIO3_A6_d, 122 LCDC_D12/VOP_BT1120_D4/GMAC1_RXD3_M0/I2S3_SDO_M0/SDMMC2_CMD_M1/GPIO3_A5_d (power), 123 LCDC_D11/VOP_BT1120_D3/GMAC1_RXD2_M0/I2S3_LRCK_M0/SDMMC2_D3_M1/GPIO3_A4_d, 124 LCDC_D10/VOP_BT1120_D2/GMAC1_TXD3_M0/I2S3_SCLK_M0/SDMMC2_D2_M1/GPIO3_A3_d, 125 LCDC_D9/VOP_BT1120_D1/GMAC1_TXD2_M0/I2S3_MCLK_M0/SDMMC2_D1_M1/GPIO3_A2_d, 126 LCDC_D8/VOP_BT1120_D0/SPI1_CS0_M1/PCIE30X1_PERSTn_M1/SDMMC2_D0_M1/GPIO3_A1_d, 127 GND7, 128 MIPI_DSI_TX1_D3N, 129 MIPI_DSI_TX1_D3P, 130 MIPI_DSI_TX1_D2N (power), 131 MIPI_DSI_TX1_D2P, 132 MIPI_DSI_TX1_CLKN, 133 MIPI_DSI_TX1_CLKP, 134 MIPI_DSI_TX1_D1N, 135 MIPI_DSI_TX1_D1P, 136 MIPI_DSI_TX1_D0N, 137 MIPI_DSI_TX1_D0P, 138 MIPI_DSI_TX0_D3N/LVDS_TX0_D3N, 139 MIPI_DSI_TX0_D3N/LVDS_TX0_D3P, 140 MIPI_DSI_TX0_D2N/LVDS_TX0_D2N, 141 MIPI_DSI_TX0_D2N/LVDS_TX0_D2P (power), 142 MIPI_DSI_TX0_CLKN/LVDS_TX0_CLKN (power), 143 MIPI_DSI_TX0_CLKN/LVDS_TX0_CLKP, 144 MIPI_DSI_TX0_D1N/LVDS_TX0_D1N, 145 MIPI_DSI_TX0_D1N/LVDS_TX0_D1P (power), 146 MIPI_DSI_TX0_D0N/LVDS_TX0_D0N (power), 147 MIPI_DSI_TX0_D0N/LVDS_TX0_D0P (power), 148 HDMI_TX_HPDIN (power), 149 HDMITX_SDA/I2C5_SDA_M1/GPIO4_D0_u, 150 HDMITX_SCL/I2C5_SCL_M1/GPIO4_C7_u, 151 HDMITX_CEC_M0/SPI3_CS1_M1/GPIO4_D1_u, 152 GND8, 153 HDMI_TX_CLKN, 154 HDMI_TX_CLKP, 155 HDMI_TX_D0N, 156 HDMI_TX_D0P, 157 HDMI_TX_D1N, 158 HDMI_TX_D1P, 159 HDMI_TX_D2N, 160 HDMI_TX_D2P (power), 161 MIPI_CSI_RX_D0P/PCIE30_TX0P, 162 MIPI_CSI_RX_D0N/PCIE30_TX0N, 163 MIPI_CSI_RX_D1P/PCIE30_TX1P, 164 MIPI_CSI_RX_D1N/PCIE30_TX1N, 165 MIPI_CSI_RX_D2P/PCIE30_RX0P, 166 MIPI_CSI_RX_D2N/PCIE30_RX0N, 167 MIPI_CSI_RX_D3P/PCIE30_RX1P, 168 MIPI_CSI_RX_D3N/PCIE30_RX1N, 169 MIPI_CSI_RX_CLK0P/PCIE30_REFCLKP_IN, 170 MIPI_CSI_RX_CLK0N/PCIE30_REFCLKN_IN, 171 MIPI_CSI_RX_CLK1P, 172 MIPI_CSI_RX_CLK1N, 173 PCIE20_TXP/SATA2_TXP/QSGMII_TXP_M1, 174 PCIE20_TXN/SATA2_TXN/QSGMII_TXN_M1, 175 PCIE20_RXP/SATA2_RXP/QSGMII_RXP_M1, 176 PCIE20_RXN/SATA2_RXN/QSGMII_RXN_M1, 177 PCIE20_REFCLKP, 178 PCIE20_REFCLKN, 179 GND9, 180 USB3_HOST1_SSTXP/SATA1_TXP/QSGMII_TXP_M0, 181 USB3_HOST1_SSTXN/SATA1_TXN/QSGMII_TXN_M0, 182 USB3_HOST1_DM, 183 USB3_HOST1_DP, 184 USB3_HOST1_SSRXP/SATA1_RXP/QSGMII_RXP_M0, 185 USB3_HOST1_SSRXN/SATA1_RXN/QSGMII_RXN_M0, 186 USB3_OTG0_SSTXP/SATA0_TXP, 187 USB3_OTG0_SSTXN/SATA0_TXN, 188 USB3_OTG0_DM, 189 USB3_OTG0_DP, 190 USB3_OTG0_SSRXP/SATA0_RXP, 191 USB3_OTG0_SSRXN/SATA0_RXN, 192 USB3_OTG0_VBUSDET, 193 USB3_OTG0_ID, 194 GND10, 195 EDP_TX_D3N, 196 EDP_TX_D3P, 197 EDP_TX_AUXN, 198 EDP_TX_AUXP, 199 EDP_TX_D2N, 200 EDP_TX_D2P, 201 EDP_TX_D1N, 202 EDP_TX_D1P (power), 203 EDP_TX_D0N, 204 EDP_TX_D0P

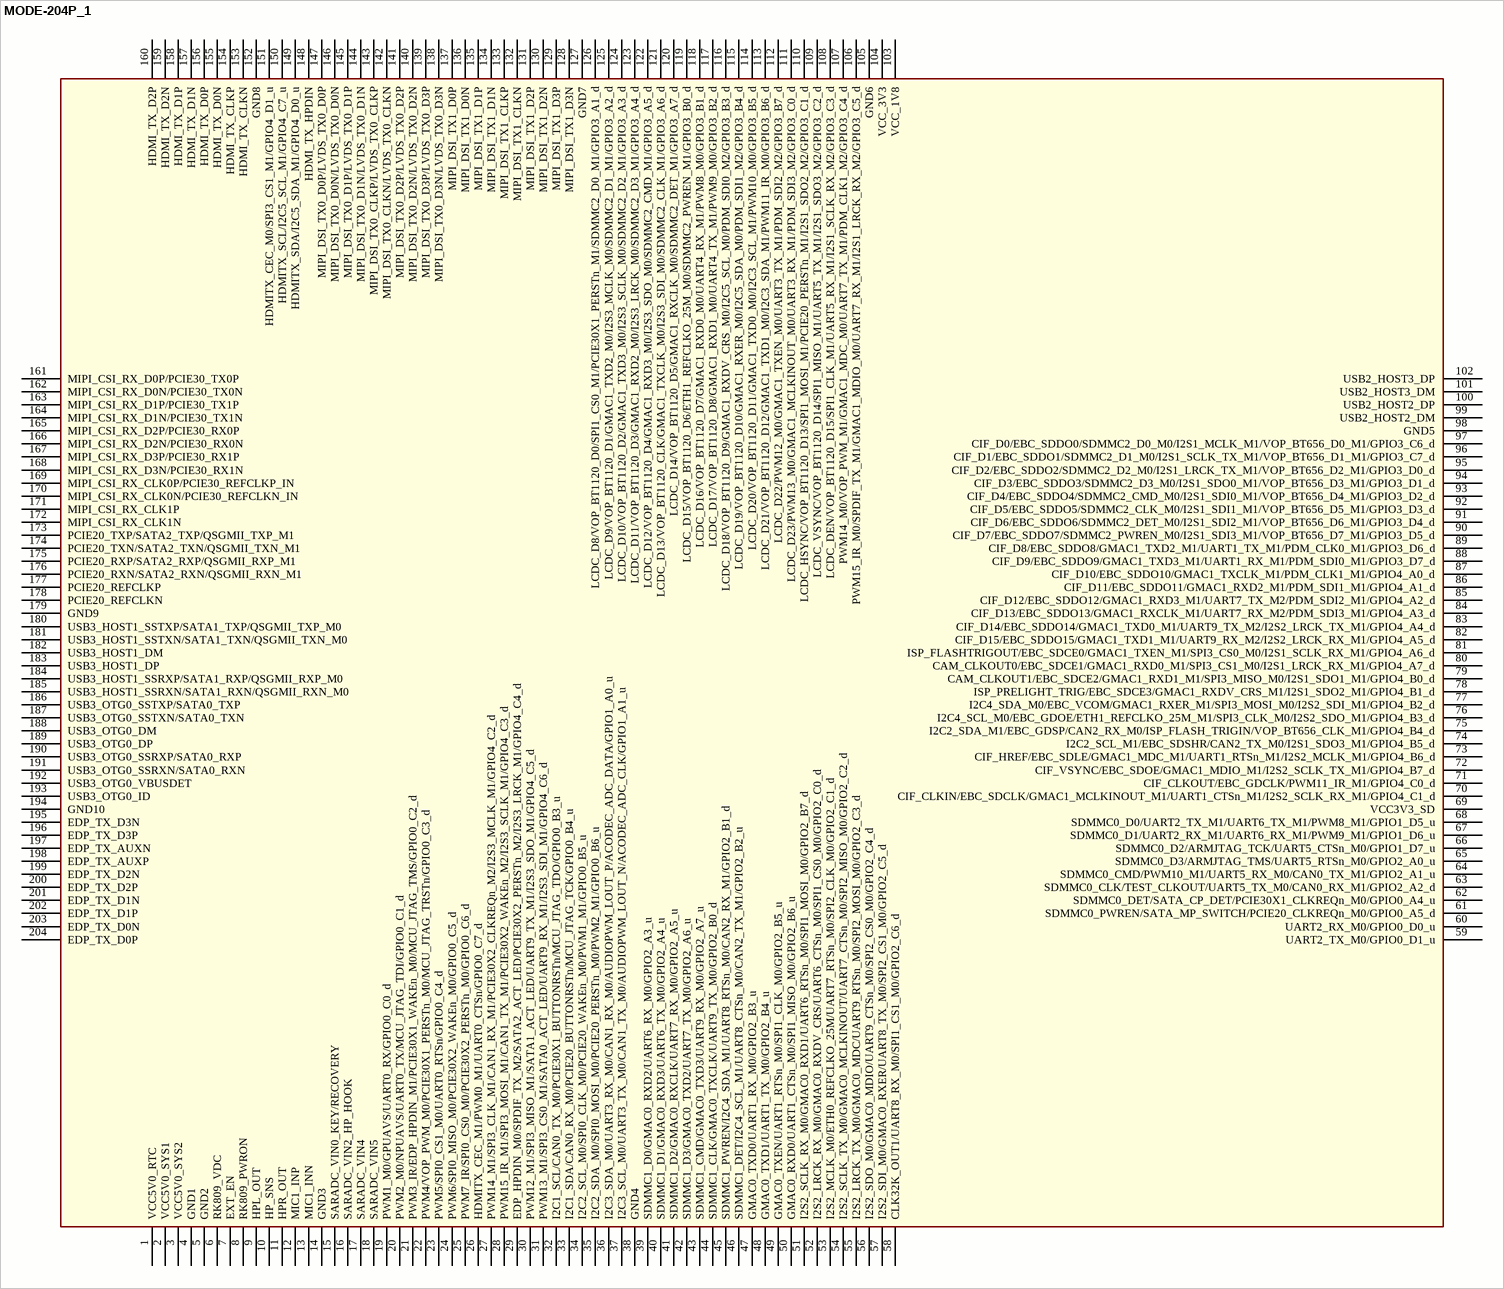
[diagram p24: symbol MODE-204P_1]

## MODE-204P_1
designator M?
Altium-Right: 1060; Altium-Bottom: 880
pins: 1 VCC5V0_RTC, 2 VCC5V0_SYS1, 3 VCC5V0_SYS2 (power), 4 GND1, 5 GND2, 6 RK809_VDC, 7 EXT_EN, 8 RK809_PWRON, 9 HPL_OUT, 10 HP_SNS, 11 HPR_OUT, 12 MIC1_INP, 13 MIC1_INN, 14 GND3, 15 SARADC_VIN0_KEY/RECOVERY, 16 SARADC_VIN2_HP_HOOK, 17 SARADC_VIN4, 18 SARADC_VIN5, 19 PWM1_M0/GPUAVS/UART0_RX/GPIO0_C0_d, 20 PWM2_M0/NPUAVS/UART0_TX/MCU_JTAG_TDI/GPIO0_C1_d, 21 PWM3_IR/EDP_HPDIN_M1/PCIE30X1_WAKEn_M0/MCU_JTAG_TMS/GPIO0_C2_d, 22 PWM4/VOP_PWM_M0/PCIE30X1_PERSTn_M0/MCU_JTAG_TRSTn/GPIO0_C3_d, 23 PWM5/SPI0_CS1_M0/UART0_RTSn/GPIO0_C4_d, 24 PWM6/SPI0_MISO_M0/PCIE30X2_WAKEn_M0/GPIO0_C5_d, 25 PWM7_IR/SPI0_CS0_M0/PCIE30X2_PERSTn_M0/GPIO0_C6_d, 26 HDMITX_CEC_M1/PWM0_M1/UART0_CTSn/GPIO0_C7_d (power), 27 PWM14_M1/SPI3_CLK_M1/CAN1_RX_M1/PCIE30X2_CLKREQn_M2/I2S3_MCLK_M1/GPIO4_C2_d, 28 PWM15_IR_M1/SPI3_MOSI_M1/CAN1_TX_M1/PCIE30X2_WAKEn_M2/I2S3_SCLK_M1/GPIO4_C3_d, 29 EDP_HPDIN_M0/SPDIF_TX_M2/SATA2_ACT_LED/PCIE30X2_PERSTn_M2/I2S3_LRCK_M1/GPIO4_C4_d, 30 PWM12_M1/SPI3_MISO_M1/SATA1_ACT_LED/UART9_TX_M1/I2S3_SDO_M1/GPIO4_C5_d, 31 PWM13_M1/SPI3_CS0_M1/SATA0_ACT_LED/UART9_RX_M1/I2S3_SDI_M1/GPIO4_C6_d, 32 I2C1_SCL/CAN0_TX_M0/PCIE30X1_BUTTONRSTn/MCU_JTAG_TDO/GPIO0_B3_u, 33 I2C1_SDA/CAN0_RX_M0/PCIE20_BUTTONRSTn/MCU_JTAG_TCK/GPIO0_B4_u, 34 I2C2_SCL_M0/SPI0_CLK_M0/PCIE20_WAKEn_M0/PWM1_M1/GPIO0_B5_u, 35 I2C2_SDA_M0/SPI0_MOSI_M0/PCIE20_PERSTn_M0/PWM2_M1/GPIO0_B6_u, 36 I2C3_SDA_M0/UART3_RX_M0/CAN1_RX_M0/AUDIOPWM_LOUT_P/ACODEC_ADC_DATA/GPIO1_A0_u, 37 I2C3_SCL_M0/UART3_TX_M0/CAN1_TX_M0/AUDIOPWM_LOUT_N/ACODEC_ADC_CLK/GPIO1_A1_u, 38 GND4, 39 SDMMC1_D0/GMAC0_RXD2/UART6_RX_M0/GPIO2_A3_u, 40 SDMMC1_D1/GMAC0_RXD3/UART6_TX_M0/GPIO2_A4_u, 41 SDMMC1_D2/GMAC0_RXCLK/UART7_RX_M0/GPIO2_A5_u, 42 SDMMC1_D3/GMAC0_TXD2/UART7_TX_M0/GPIO2_A6_u, 43 SDMMC1_CMD/GMAC0_TXD3/UART9_RX_M0/GPIO2_A7_u, 44 SDMMC1_CLK/GMAC0_TXCLK/UART9_TX_M0/GPIO2_B0_d, 45 SDMMC1_PWREN/I2C4_SDA_M1/UART8_RTSn_M0/CAN2_RX_M1/GPIO2_B1_d, 46 SDMMC1_DET/I2C4_SCL_M1/UART8_CTSn_M0/CAN2_TX_M1/GPIO2_B2_u, 47 GMAC0_TXD0/UART1_RX_M0/GPIO2_B3_u, 48 GMAC0_TXD1/UART1_TX_M0/GPIO2_B4_u (power), 49 GMAC0_TXEN/UART1_RTSn_M0/SPI1_CLK_M0/GPIO2_B5_u (power), 50 GMAC0_RXD0/UART1_CTSn_M0/SPI1_MISO_M0/GPIO2_B6_u, 51 I2S2_SCLK_RX_M0/GMAC0_RXD1/UART6_RTSn_M0/SPI1_MOSI_M0/GPIO2_B7_d, 52 I2S2_LRCK_RX_M0/GMAC0_RXDV_CRS/UART6_CTSn_M0/SPI1_CS0_M0/GPIO2_C0_d, 53 I2S2_MCLK_M0/ETH0_REFCLKO_25M/UART7_RTSn_M0/SPI2_CLK_M0/GPIO2_C1_d, 54 I2S2_SCLK_TX_M0/GMAC0_MCLKINOUT/UART7_CTSn_M0/SPI2_MISO_M0/GPIO2_C2_d, 55 I2S2_LRCK_TX_M0/GMAC0_MDC/UART9_RTSn_M0/SPI2_MOSI_M0/GPIO2_C3_d, 56 I2S2_SDO_M0/GMAC0_MDIO/UART9_CTSn_M0/SPI2_CS0_M0/GPIO2_C4_d, 57 I2S2_SDI_M0/GMAC0_RXER/UART8_TX_M0/SPI2_CS1_M0/GPIO2_C5_d, 58 CLK32K_OUT1/UART8_RX_M0/SPI1_CS1_M0/GPIO2_C6_d, 59 UART2_TX_M0/GPIO0_D1_u, 60 UART2_RX_M0/GPIO0_D0_u, 61 SDMMC0_PWREN/SATA_MP_SWITCH/PCIE20_CLKREQn_M0/GPIO0_A5_d, 62 SDMMC0_DET/SATA_CP_DET/PCIE30X1_CLKREQn_M0/GPIO0_A4_u, 63 SDMMC0_CLK/TEST_CLKOUT/UART5_TX_M0/CAN0_RX_M1/GPIO2_A2_d, 64 SDMMC0_CMD/PWM10_M1/UART5_RX_M0/CAN0_TX_M1/GPIO2_A1_u (power), 65 SDMMC0_D3/ARMJTAG_TMS/UART5_RTSn_M0/GPIO2_A0_u, 66 SDMMC0_D2/ARMJTAG_TCK/UART5_CTSn_M0/GPIO1_D7_u, 67 SDMMC0_D1/UART2_RX_M1/UART6_RX_M1/PWM9_M1/GPIO1_D6_u, 68 SDMMC0_D0/UART2_TX_M1/UART6_TX_M1/PWM8_M1/GPIO1_D5_u, 69 VCC3V3_SD, 70 CIF_CLKIN/EBC_SDCLK/GMAC1_MCLKINOUT_M1/UART1_CTSn_M1/I2S2_SCLK_RX_M1/GPIO4_C1_d, 71 CIF_CLKOUT/EBC_GDCLK/PWM11_IR_M1/GPIO4_C0_d, 72 CIF_VSYNC/EBC_SDOE/GMAC1_MDIO_M1/I2S2_SCLK_TX_M1/GPIO4_B7_d, 73 CIF_HREF/EBC_SDLE/GMAC1_MDC_M1/UART1_RTSn_M1/I2S2_MCLK_M1/GPIO4_B6_d, 74 I2C2_SCL_M1/EBC_SDSHR/CAN2_TX_M0/I2S1_SDO3_M1/GPIO4_B5_d, 75 I2C2_SDA_M1/EBC_GDSP/CAN2_RX_M0/ISP_FLASH_TRIGIN/VOP_BT656_CLK_M1/GPIO4_B4_d, 76 I2C4_SCL_M0/EBC_GDOE/ETH1_REFCLKO_25M_M1/SPI3_CLK_M0/I2S2_SDO_M1/GPIO4_B3_d, 77 I2C4_SDA_M0/EBC_VCOM/GMAC1_RXER_M1/SPI3_MOSI_M0/I2S2_SDI_M1/GPIO4_B2_d, 78 ISP_PRELIGHT_TRIG/EBC_SDCE3/GMAC1_RXDV_CRS_M1/I2S1_SDO2_M1/GPIO4_B1_d (power), 79 CAM_CLKOUT1/EBC_SDCE2/GMAC1_RXD1_M1/SPI3_MISO_M0/I2S1_SDO1_M1/GPIO4_B0_d, 80 CAM_CLKOUT0/EBC_SDCE1/GMAC1_RXD0_M1/SPI3_CS1_M0/I2S1_LRCK_RX_M1/GPIO4_A7_d, 81 ISP_FLASHTRIGOUT/EBC_SDCE0/GMAC1_TXEN_M1/SPI3_CS0_M0/I2S1_SCLK_RX_M1/GPIO4_A6_d, 82 CIF_D15/EBC_SDDO15/GMAC1_TXD1_M1/UART9_RX_M2/I2S2_LRCK_RX_M1/GPIO4_A5_d, 83 CIF_D14/EBC_SDDO14/GMAC1_TXD0_M1/UART9_TX_M2/I2S2_LRCK_TX_M1/GPIO4_A4_d, 84 CIF_D13/EBC_SDDO13/GMAC1_RXCLK_M1/UART7_RX_M2/PDM_SDI3_M1/GPIO4_A3_d, 85 CIF_D12/EBC_SDDO12/GMAC1_RXD3_M1/UART7_TX_M2/PDM_SDI2_M1/GPIO4_A2_d, 86 CIF_D11/EBC_SDDO11/GMAC1_RXD2_M1/PDM_SDI1_M1/GPIO4_A1_d, 87 CIF_D10/EBC_SDDO10/GMAC1_TXCLK_M1/PDM_CLK1_M1/GPIO4_A0_d, 88 CIF_D9/EBC_SDDO9/GMAC1_TXD3_M1/UART1_RX_M1/PDM_SDI0_M1/GPIO3_D7_d, 89 CIF_D8/EBC_SDDO8/GMAC1_TXD2_M1/UART1_TX_M1/PDM_CLK0_M1/GPIO3_D6_d, 90 CIF_D7/EBC_SDDO7/SDMMC2_PWREN_M0/I2S1_SDI3_M1/VOP_BT656_D7_M1/GPIO3_D5_d, 91 CIF_D6/EBC_SDDO6/SDMMC2_DET_M0/I2S1_SDI2_M1/VOP_BT656_D6_M1/GPIO3_D4_d, 92 CIF_D5/EBC_SDDO5/SDMMC2_CLK_M0/I2S1_SDI1_M1/VOP_BT656_D5_M1/GPIO3_D3_d, 93 CIF_D4/EBC_SDDO4/SDMMC2_CMD_M0/I2S1_SDI0_M1/VOP_BT656_D4_M1/GPIO3_D2_d, 94 CIF_D3/EBC_SDDO3/SDMMC2_D3_M0/I2S1_SDO0_M1/VOP_BT656_D3_M1/GPIO3_D1_d, 95 CIF_D2/EBC_SDDO2/SDMMC2_D2_M0/I2S1_LRCK_TX_M1/VOP_BT656_D2_M1/GPIO3_D0_d, 96 CIF_D1/EBC_SDDO1/SDMMC2_D1_M0/I2S1_SCLK_TX_M1/VOP_BT656_D1_M1/GPIO3_C7_d, 97 CIF_D0/EBC_SDDO0/SDMMC2_D0_M0/I2S1_MCLK_M1/VOP_BT656_D0_M1/GPIO3_C6_d, 98 GND5, 99 USB2_HOST2_DM, 100 USB2_HOST2_DP, 101 USB2_HOST3_DM (power), 102 USB2_HOST3_DP, 103 VCC_1V8, 104 VCC_3V3, 105 GND6, 106 PWM15_IR_M0/SPDIF_TX_M1/GMAC1_MDIO_M0/UART7_RX_M1/I2S1_LRCK_RX_M2/GPIO3_C5_d, 107 PWM14_M0/VOP_PWM_M1/GMAC1_MDC_M0/UART7_TX_M1/PDM_CLK1_M2/GPIO3_C4_d, 108 LCDC_DEN/VOP_BT1120_D15/SPI1_CLK_M1/UART5_RX_M1/I2S1_SCLK_RX_M2/GPIO3_C3_d, 109 LCDC_VSYNC/VOP_BT1120_D14/SPI1_MISO_M1/UART5_TX_M1/I2S1_SDO3_M2/GPIO3_C2_d, 110 LCDC_HSYNC/VOP_BT1120_D13/SPI1_MOSI_M1/PCIE20_PERSTn_M1/I2S1_SDO2_M2/GPIO3_C1_d, 111 LCDC_D23/PWM13_M0/GMAC1_MCLKINOUT_M0/UART3_RX_M1/PDM_SDI3_M2/GPIO3_C0_d, 112 LCDC_D22/PWM12_M0/GMAC1_TXEN_M0/UART3_TX_M1/PDM_SDI2_M2/GPIO3_B7_d, 113 LCDC_D21/VOP_BT1120_D12/GMAC1_TXD1_M0/I2C3_SDA_M1/PWM11_IR_M0/GPIO3_B6_d, 114 LCDC_D20/VOP_BT1120_D11/GMAC1_TXD0_M0/I2C3_SCL_M1/PWM10_M0/GPIO3_B5_d, 115 LCDC_D19/VOP_BT1120_D10/GMAC1_RXER_M0/I2C5_SDA_M0/PDM_SDI1_M2/GPIO3_B4_d, 116 LCDC_D18/VOP_BT1120_D9/GMAC1_RXDV_CRS_M0/I2C5_SCL_M0/PDM_SDI0_M2/GPIO3_B3_d, 117 LCDC_D17/VOP_BT1120_D8/GMAC1_RXD1_M0/UART4_TX_M1/PWM9_M0/GPIO3_B2_d, 118 LCDC_D16/VOP_BT1120_D7/GMAC1_RXD0_M0/UART4_RX_M1/PWM8_M0/GPIO3_B1_d, 119 LCDC_D15/VOP_BT1120_D6/ETH1_REFCLKO_25M_M0/SDMMC2_PWREN_M1/GPIO3_B0_d, 120 LCDC_D14/VOP_BT1120_D5/GMAC1_RXCLK_M0/SDMMC2_DET_M1/GPIO3_A7_d, 121 LCDC_D13/VOP_BT1120_CLK/GMAC1_TXCLK_M0/I2S3_SDI_M0/SDMMC2_CLK_M1/GPIO3_A6_d, 122 LCDC_D12/VOP_BT1120_D4/GMAC1_RXD3_M0/I2S3_SDO_M0/SDMMC2_CMD_M1/GPIO3_A5_d (power), 123 LCDC_D11/VOP_BT1120_D3/GMAC1_RXD2_M0/I2S3_LRCK_M0/SDMMC2_D3_M1/GPIO3_A4_d, 124 LCDC_D10/VOP_BT1120_D2/GMAC1_TXD3_M0/I2S3_SCLK_M0/SDMMC2_D2_M1/GPIO3_A3_d, 125 LCDC_D9/VOP_BT1120_D1/GMAC1_TXD2_M0/I2S3_MCLK_M0/SDMMC2_D1_M1/GPIO3_A2_d, 126 LCDC_D8/VOP_BT1120_D0/SPI1_CS0_M1/PCIE30X1_PERSTn_M1/SDMMC2_D0_M1/GPIO3_A1_d, 127 GND7, 128 MIPI_DSI_TX1_D3N, 129 MIPI_DSI_TX1_D3P, 130 MIPI_DSI_TX1_D2N (power), 131 MIPI_DSI_TX1_D2P, 132 MIPI_DSI_TX1_CLKN, 133 MIPI_DSI_TX1_CLKP, 134 MIPI_DSI_TX1_D1N, 135 MIPI_DSI_TX1_D1P, 136 MIPI_DSI_TX1_D0N, 137 MIPI_DSI_TX1_D0P, 138 MIPI_DSI_TX0_D3N/LVDS_TX0_D3N, 139 MIPI_DSI_TX0_D3P/LVDS_TX0_D3P, 140 MIPI_DSI_TX0_D2N/LVDS_TX0_D2N, 141 MIPI_DSI_TX0_D2P/LVDS_TX0_D2P (power), 142 MIPI_DSI_TX0_CLKN/LVDS_TX0_CLKN (power), 143 MIPI_DSI_TX0_CLKP/LVDS_TX0_CLKP, 144 MIPI_DSI_TX0_D1N/LVDS_TX0_D1N, 145 MIPI_DSI_TX0_D1P/LVDS_TX0_D1P (power), 146 MIPI_DSI_TX0_D0N/LVDS_TX0_D0N (power), 147 MIPI_DSI_TX0_D0P/LVDS_TX0_D0P (power), 148 HDMI_TX_HPDIN (power), 149 HDMITX_SDA/I2C5_SDA_M1/GPIO4_D0_u, 150 HDMITX_SCL/I2C5_SCL_M1/GPIO4_C7_u, 151 HDMITX_CEC_M0/SPI3_CS1_M1/GPIO4_D1_u, 152 GND8, 153 HDMI_TX_CLKN, 154 HDMI_TX_CLKP, 155 HDMI_TX_D0N, 156 HDMI_TX_D0P, 157 HDMI_TX_D1N, 158 HDMI_TX_D1P, 159 HDMI_TX_D2N, 160 HDMI_TX_D2P (power), 161 MIPI_CSI_RX_D0P/PCIE30_TX0P, 162 MIPI_CSI_RX_D0N/PCIE30_TX0N, 163 MIPI_CSI_RX_D1P/PCIE30_TX1P, 164 MIPI_CSI_RX_D1N/PCIE30_TX1N, 165 MIPI_CSI_RX_D2P/PCIE30_RX0P, 166 MIPI_CSI_RX_D2N/PCIE30_RX0N, 167 MIPI_CSI_RX_D3P/PCIE30_RX1P, 168 MIPI_CSI_RX_D3N/PCIE30_RX1N, 169 MIPI_CSI_RX_CLK0P/PCIE30_REFCLKP_IN, 170 MIPI_CSI_RX_CLK0N/PCIE30_REFCLKN_IN, 171 MIPI_CSI_RX_CLK1P, 172 MIPI_CSI_RX_CLK1N, 173 PCIE20_TXP/SATA2_TXP/QSGMII_TXP_M1, 174 PCIE20_TXN/SATA2_TXN/QSGMII_TXN_M1, 175 PCIE20_RXP/SATA2_RXP/QSGMII_RXP_M1, 176 PCIE20_RXN/SATA2_RXN/QSGMII_RXN_M1, 177 PCIE20_REFCLKP, 178 PCIE20_REFCLKN, 179 GND9, 180 USB3_HOST1_SSTXP/SATA1_TXP/QSGMII_TXP_M0, 181 USB3_HOST1_SSTXN/SATA1_TXN/QSGMII_TXN_M0, 182 USB3_HOST1_DM, 183 USB3_HOST1_DP, 184 USB3_HOST1_SSRXP/SATA1_RXP/QSGMII_RXP_M0, 185 USB3_HOST1_SSRXN/SATA1_RXN/QSGMII_RXN_M0, 186 USB3_OTG0_SSTXP/SATA0_TXP, 187 USB3_OTG0_SSTXN/SATA0_TXN, 188 USB3_OTG0_DM, 189 USB3_OTG0_DP, 190 USB3_OTG0_SSRXP/SATA0_RXP, 191 USB3_OTG0_SSRXN/SATA0_RXN, 192 USB3_OTG0_VBUSDET, 193 USB3_OTG0_ID, 194 GND10, 195 EDP_TX_D3N, 196 EDP_TX_D3P, 197 EDP_TX_AUXN, 198 EDP_TX_AUXP, 199 EDP_TX_D2N, 200 EDP_TX_D2P, 201 EDP_TX_D1N, 202 EDP_TX_D1P (power), 203 EDP_TX_D0N, 204 EDP_TX_D0P

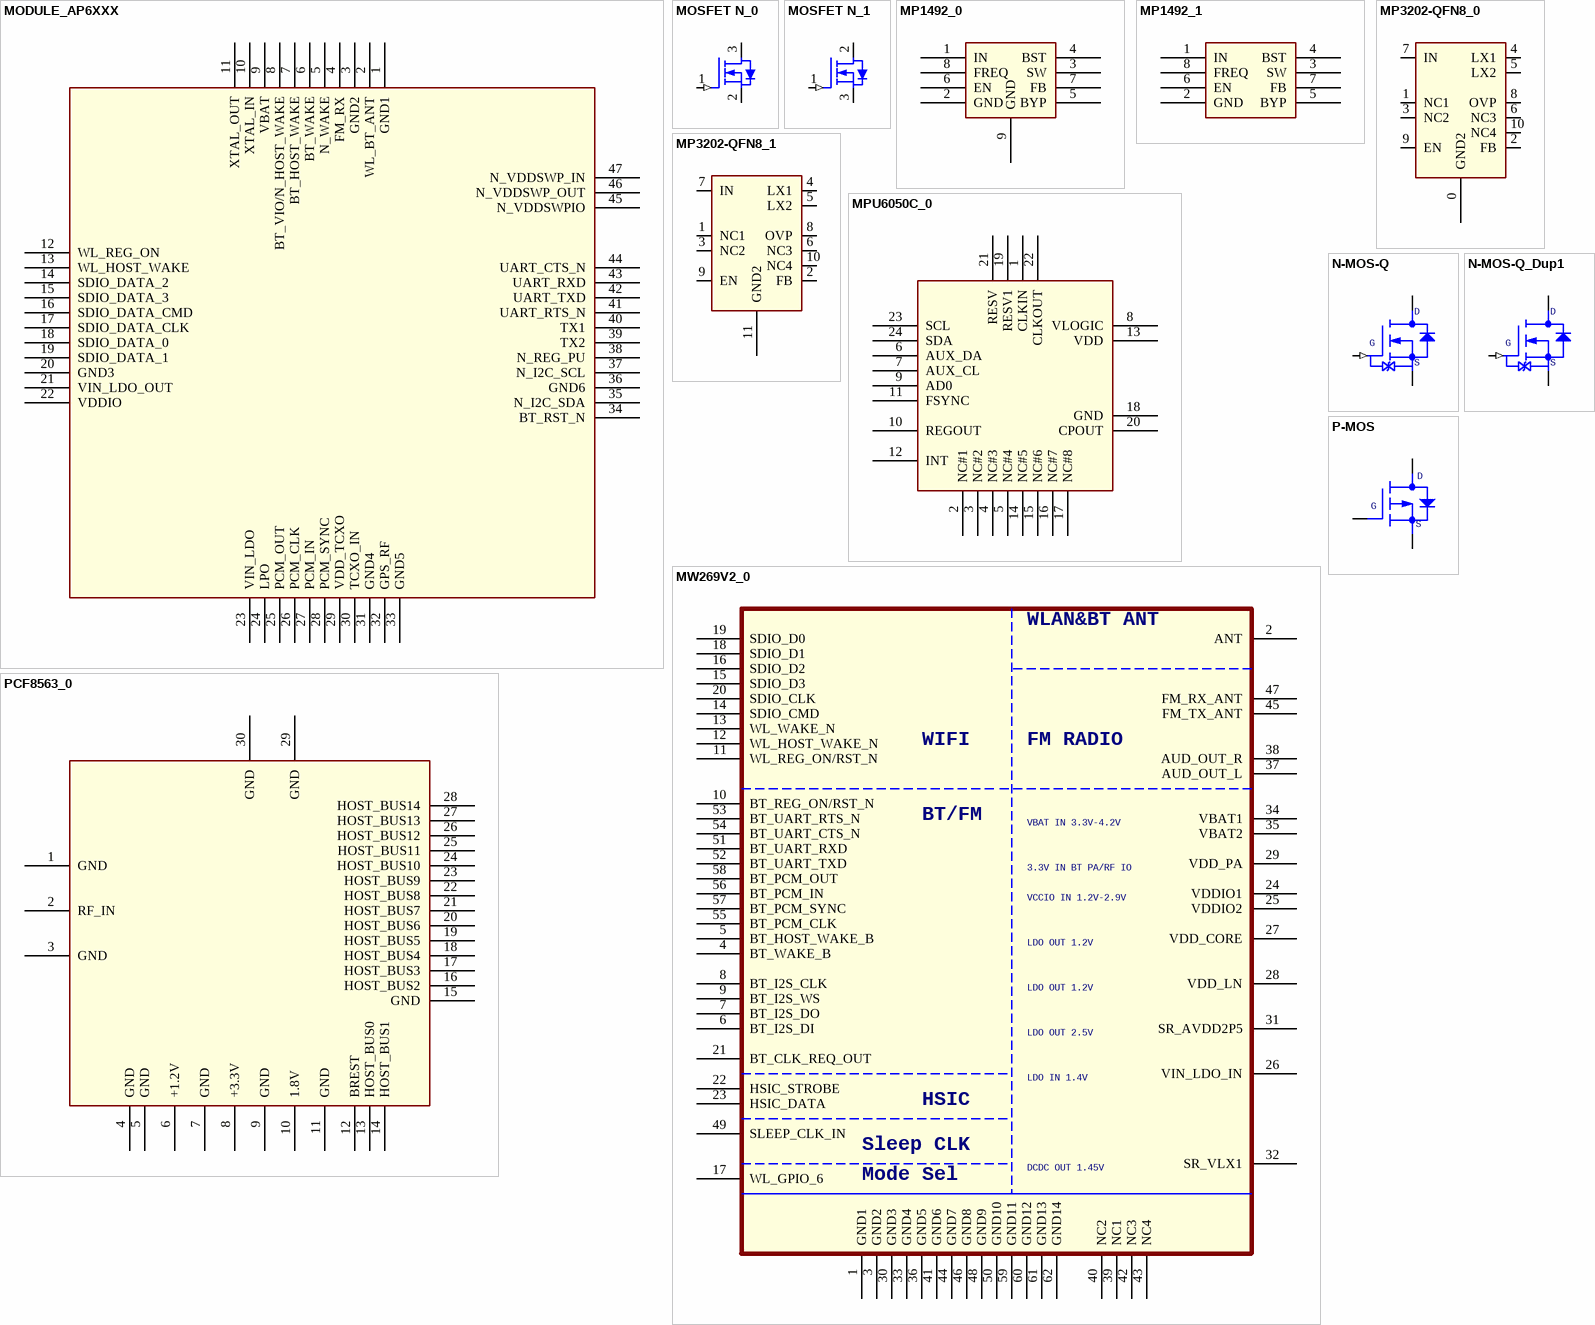
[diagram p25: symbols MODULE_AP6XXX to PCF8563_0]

## MODULE_AP6XXX
designator U?
Altium-Right: 350; Altium-Bottom: 340
pins: 1 GND1, 2 WL_BT_ANT, 3 GND2, 4 FM_RX, 5 N_WAKE, 6 BT_WAKE, 7 BT_HOST_WAKE, 8 BT_VIO/N_HOST_WAKE, 9 VBAT, 10 XTAL_IN, 11 XTAL_OUT, 12 WL_REG_ON, 13 WL_HOST_WAKE, 14 SDIO_DATA_2, 15 SDIO_DATA_3, 16 SDIO_DATA_CMD, 17 SDIO_DATA_CLK, 18 SDIO_DATA_0, 19 SDIO_DATA_1, 20 GND3, 21 VIN_LDO_OUT, 22 VDDIO, 23 VIN_LDO, 24 LPO, 25 PCM_OUT, 26 PCM_CLK, 27 PCM_IN, 28 PCM_SYNC, 29 VDD_TCXO, 30 TCXO_IN, 31 GND4, 32 GPS_RF, 33 GND5, 34 BT_RST_N, 35 N_I2C_SDA, 36 GND6, 37 N_I2C_SCL, 38 N_REG_PU, 39 TX2, 40 TX1, 41 UART_RTS_N, 42 UART_TXD, 43 UART_RXD, 44 UART_CTS_N, 45 N_VDDSWPIO, 46 N_VDDSWP_OUT, 47 N_VDDSWP_IN

## MOSFET N_0
designator Q?
Altium-Right: 30; Altium-Bottom: 20
pins: 1 GATE (in), 2 SOURCE, 3 DRAIN

## MOSFET N_1
designator Q?
Altium-Right: 30; Altium-Bottom: 20
pins: 1 GATE (in), 2 DRAIN, 3 SOURCE

## MP1492_0
designator U?
Altium-Right: 60; Altium-Bottom: 50
footprint SOP8A
pins: 1 IN, 2 GND, 3 SW, 4 BST, 5 BYP, 6 EN, 7 FB, 8 FREQ, 9 GND

## MP1492_1
designator U?
Altium-Right: 60; Altium-Bottom: 50
footprint SOP8A
pins: 1 IN, 2 GND, 3 SW, 4 BST, 5 BYP, 6 EN, 7 FB, 8 FREQ

## MP3202-QFN8_0
designator U?
Altium-Right: 60; Altium-Bottom: 90
footprint QFN8-2X2
pins: 0 GND2, 1 NC1, 2 FB, 3 NC2, 4 LX1, 5 LX2, 6 NC3, 7 IN, 8 OVP, 9 EN, 10 NC4

## MP3202-QFN8_1
designator U?
Altium-Right: 60; Altium-Bottom: 90
footprint QFN8-2X2
pins: 1 NC1, 2 FB, 3 NC2, 4 LX1, 5 LX2, 6 NC3, 7 IN, 8 OVP, 9 EN, 10 NC4, 11 GND2

## MPU6050C_0
designator U?
Altium-Right: 130; Altium-Bottom: 140
pins: 1 CLKIN, 2 NC#1, 3 NC#2, 4 NC#3, 5 NC#4, 6 AUX_DA, 7 AUX_CL, 8 VLOGIC, 9 AD0, 10 REGOUT, 11 FSYNC, 12 INT, 13 VDD, 14 NC#5, 15 NC#6, 16 NC#7, 17 NC#8, 18 GND, 19 RESV1, 20 CPOUT, 21 RESV, 22 CLKOUT, 23 SCL, 24 SDA

## MW269V2_0
designator U?
Altium-Right: 340; Altium-Bottom: 430
footprint MW269V2
pins: 1 GND1, 2 ANT, 3 GND2, 4 BT_WAKE_B, 5 BT_HOST_WAKE_B, 6 BT_I2S_DI, 7 BT_I2S_DO, 8 BT_I2S_CLK, 9 BT_I2S_WS, 10 BT_REG_ON/RST_N, 11 WL_REG_ON/RST_N, 12 WL_HOST_WAKE_N, 13 WL_WAKE_N, 14 SDIO_CMD, 15 SDIO_D3, 16 SDIO_D2, 17 WL_GPIO_6, 18 SDIO_D1, 19 SDIO_D0, 20 SDIO_CLK, 21 BT_CLK_REQ_OUT, 22 HSIC_STROBE, 23 HSIC_DATA, 24 VDDIO1, 25 VDDIO2, 26 VIN_LDO_IN, 27 VDD_CORE, 28 VDD_LN, 29 VDD_PA, 30 GND3, 31 SR_AVDD2P5, 32 SR_VLX1, 33 GND4, 34 VBAT1, 35 VBAT2, 36 GND5, 37 AUD_OUT_L, 38 AUD_OUT_R, 39 NC1, 40 NC2, 41 GND6, 42 NC3, 43 NC4, 44 GND7, 45 FM_TX_ANT, 46 GND8, 47 FM_RX_ANT, 48 GND9, 49 SLEEP_CLK_IN, 50 GND10, 51 BT_UART_RXD, 52 BT_UART_TXD, 53 BT_UART_RTS_N, 54 BT_UART_CTS_N, 55 BT_PCM_CLK, 56 BT_PCM_IN, 57 BT_PCM_SYNC, 58 BT_PCM_OUT, 59 GND11, 60 GND12, 61 GND13, 62 GND14

## N-MOS-Q
designator Q?
Altium-Right: 50; Altium-Bottom: 40
pins: 1 GATE (in), 2 SOURCE, 3 DRAIN

## N-MOS-Q_Dup1
designator Q?
Altium-Right: 50; Altium-Bottom: 40
pins: 1 GATE (in), 2 SOURCE, 3 DRAIN

## P-MOS
designator Q?
Altium-Right: 50; Altium-Bottom: 40
pins: 1 GATE, 2 SOURCE, 3 DRAIN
